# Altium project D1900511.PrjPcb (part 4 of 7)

## Sheet ISC_R5_SH3.SchDoc: ISC System Wiring Diagram
size B; DrawnBy: Filiberto Clara; Engineer: Filiberto Clara; Organization: LIGO Laboratory; Address1: California Institute of Technology; Address2: Massachusetts Institute of Technology; DocumentNumber: D1900511; Revision: V11; SheetNumber: 21; SheetTotal: 39
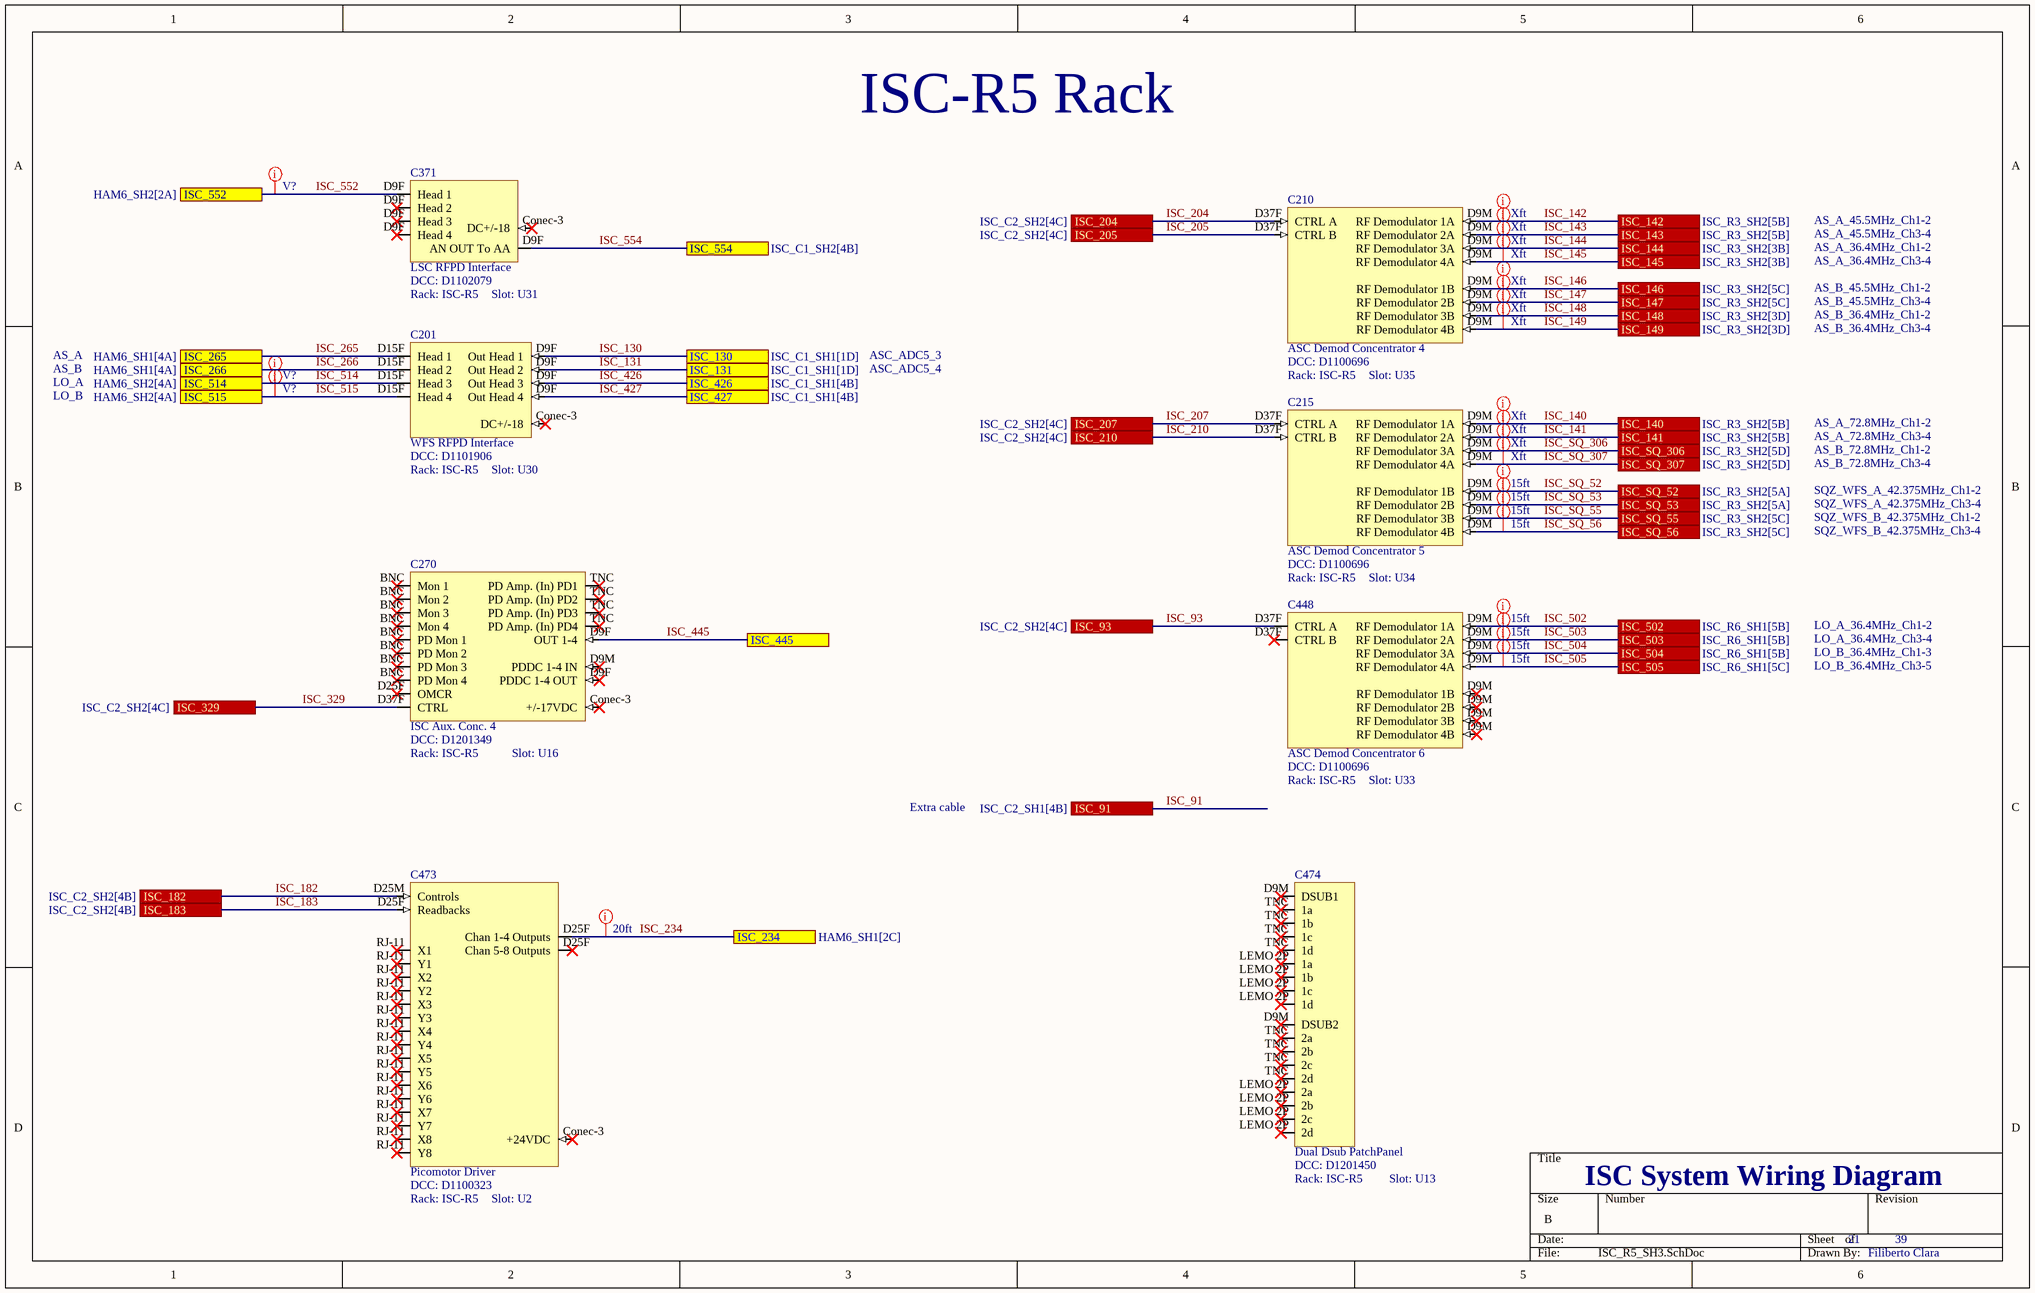
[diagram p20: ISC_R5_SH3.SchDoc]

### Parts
C201  WFS RFPD Interface  DCC: D1101906  Rack: ISC-R5  Slot: U30
C210  ASC Demod Concentrator 4  DCC: D1100696  Rack: ISC-R5  Slot: U35
C215  ASC Demod Concentrator 5  DCC: D1100696  Rack: ISC-R5  Slot: U34
C270  ISC Aux. Conc. 4  DCC: D1201349  Rack: ISC-R5  Slot: U16
C371  LSC RFPD Interface  DCC: D1102079  Rack: ISC-R5  Slot: U31
C448  ASC Demod Concentrator 6  DCC: D1100696  Rack: ISC-R5  Slot: U33
C473  Picomotor Driver  DCC: D1100323  Rack: ISC-R5  Slot: U2
C474  Dual Dsub PatchPanel  DCC: D1201450  Rack: ISC-R5  Slot: U13

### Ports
ISC_91 (see ISC_C2_SH1[4B]), ISC_93 (see ISC_C2_SH2[4C]), ISC_130 (see ISC_C1_SH1[1D]), ISC_131 (see ISC_C1_SH1[1D]), ISC_140 (see ISC_R3_SH2[5B]), ISC_141 (see ISC_R3_SH2[5B]), ISC_142 (see ISC_R3_SH2[5B]), ISC_143 (see ISC_R3_SH2[5B]), ISC_144 (see ISC_R3_SH2[3B]), ISC_145 (see ISC_R3_SH2[3B]), ISC_146 (see ISC_R3_SH2[5C]), ISC_147 (see ISC_R3_SH2[5C]), ISC_148 (see ISC_R3_SH2[3D]), ISC_149 (see ISC_R3_SH2[3D]), ISC_182 (see ISC_C2_SH2[4B]), ISC_183 (see ISC_C2_SH2[4B]), ISC_204 (see ISC_C2_SH2[4C]), ISC_205 (see ISC_C2_SH2[4C]), ISC_207 (see ISC_C2_SH2[4C]), ISC_210 (see ISC_C2_SH2[4C]), ISC_234 (see HAM6_SH1[2C]), ISC_265 (see HAM6_SH1[4A]), ISC_266 (see HAM6_SH1[4A]), ISC_329 (see ISC_C2_SH2[4C]), ISC_426 (see ISC_C1_SH1[4B]), ISC_427 (see ISC_C1_SH1[4B]), ISC_445, ISC_502 (see ISC_R6_SH1[5B]), ISC_503 (see ISC_R6_SH1[5B]), ISC_504 (see ISC_R6_SH1[5B]), ISC_505 (see ISC_R6_SH1[5C]), ISC_514 (see HAM6_SH2[4A]), ISC_515 (see HAM6_SH2[4A]), ISC_552 (see HAM6_SH2[2A]), ISC_554 (see ISC_C1_SH2[4B]), ISC_SQ_52 (see ISC_R3_SH2[5A]), ISC_SQ_53 (see ISC_R3_SH2[5A]), ISC_SQ_55 (see ISC_R3_SH2[5C]), ISC_SQ_56 (see ISC_R3_SH2[5C]), ISC_SQ_306 (see ISC_R3_SH2[5D]), ISC_SQ_307 (see ISC_R3_SH2[5D])

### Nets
ISC_93: C448.D37F(CTRL_A) ; port ISC_93
ISC_130: C201.D9F(Out_Head_1) ; port ISC_130
ISC_131: C201.D9F(Out_Head_2) ; port ISC_131
ISC_140: C215.D9M(RF_Demodulator_1A) ; port ISC_140
ISC_141: C215.D9M(RF_Demodulator_2A) ; port ISC_141
ISC_142: C210.D9M(RF_Demodulator_1A) ; port ISC_142
ISC_143: C210.D9M(RF_Demodulator_2A) ; port ISC_143
ISC_144: C210.D9M(RF_Demodulator_3A) ; port ISC_144
ISC_145: C210.D9M(RF_Demodulator_4A) ; port ISC_145
ISC_146: C210.D9M(RF_Demodulator_1B) ; port ISC_146
ISC_147: C210.D9M(RF_Demodulator_2B) ; port ISC_147
ISC_148: C210.D9M(RF_Demodulator_3B) ; port ISC_148
ISC_149: C210.D9M(RF_Demodulator_4B) ; port ISC_149
ISC_182: C473.D25M(Controls) ; port ISC_182
ISC_183: C473.D25F(Readbacks) ; port ISC_183
ISC_204: C210.D37F(CTRL_A) ; port ISC_204
ISC_205: C210.D37F(CTRL_B) ; port ISC_205
ISC_207: C215.D37F(CTRL_A) ; port ISC_207
ISC_210: C215.D37F(CTRL_B) ; port ISC_210
ISC_234: C473.D25F(Chan_1-4_Outputs) ; port ISC_234
ISC_265: C201.D15F(Head_1) ; port ISC_265
ISC_266: C201.D15F(Head_2) ; port ISC_266
ISC_329: C270.D37F(CTRL) ; port ISC_329
ISC_426: C201.D9F(Out_Head_3) ; port ISC_426
ISC_427: C201.D9F(Out_Head_4) ; port ISC_427
ISC_445: C270.D9F(PDDC_1-4_OUT) ; port ISC_445
ISC_502: C448.D9M(RF_Demodulator_1A) ; port ISC_502
ISC_503: C448.D9M(RF_Demodulator_2A) ; port ISC_503
ISC_504: C448.D9M(RF_Demodulator_3A) ; port ISC_504
ISC_505: C448.D9M(RF_Demodulator_4A) ; port ISC_505
ISC_514: C201.D15F(Head_3) ; port ISC_514
ISC_515: C201.D15F(Head_4) ; port ISC_515
ISC_552: C371.D9F(Head_1) ; port ISC_552
ISC_554: C371.D9F(AN_OUT_To_AA) ; port ISC_554
ISC_SQ_52: C215.D9M(RF_Demodulator_1B) ; port ISC_SQ_52
ISC_SQ_53: C215.D9M(RF_Demodulator_2B) ; port ISC_SQ_53
ISC_SQ_55: C215.D9M(RF_Demodulator_3B) ; port ISC_SQ_55
ISC_SQ_56: C215.D9M(RF_Demodulator_4B) ; port ISC_SQ_56
ISC_SQ_306: C215.D9M(RF_Demodulator_3A) ; port ISC_SQ_306
ISC_SQ_307: C215.D9M(RF_Demodulator_4A) ; port ISC_SQ_307

Not connected (* = marked no-connect by the designer): C201 Conec-3(DC+/-18)*; C270 BNC(PD_Mon_1)* Conec-3(+/-17VDC)* D9M(PDDC_1-4_IN)* D25F(OMCR)* TNC(PD_Amp._(In)_PD1)*; C371 Conec-3(DC+/-18)*; C473 Conec-3(+24VDC)* RJ-11(X1)*; C474 D9M(DSUB1)* LEMO 2P(1a)* TNC(1a)*

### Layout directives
Length: V?: ISC_514, ISC_515, ISC_552
Length: 20ft: ISC_234
Length: 15ft: ISC_502, ISC_503, ISC_504, ISC_505, ISC_SQ_52, ISC_SQ_53, ISC_SQ_55, ISC_SQ_56
Length: Xft: ISC_140, ISC_141, ISC_142, ISC_143, ISC_144, ISC_145, ISC_146, ISC_147, ISC_148, ISC_149, ISC_SQ_306, ISC_SQ_307

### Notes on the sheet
- ISC-R5 Rack
- AS_A_45.5MHz_Ch1-2
- AS_A_45.5MHz_Ch3-4
- AS_A_36.4MHz_Ch1-2
- AS_A_36.4MHz_Ch3-4
- AS_B_45.5MHz_Ch1-2
- AS_A
- AS_B
- ASC_ADC5_3
- ASC_ADC5_4
- AS_B_45.5MHz_Ch3-4
- AS_B_36.4MHz_Ch1-2
- AS_B_36.4MHz_Ch3-4
- LO_A
- LO_B
- AS_A_72.8MHz_Ch1-2
- AS_A_72.8MHz_Ch3-4
- AS_B_72.8MHz_Ch1-2
- AS_B_72.8MHz_Ch3-4
- SQZ_WFS_A_42.375MHz_Ch1-2
- SQZ_WFS_A_42.375MHz_Ch3-4
- SQZ_WFS_B_42.375MHz_Ch1-2
- SQZ_WFS_B_42.375MHz_Ch3-4
- LO_A_36.4MHz_Ch1-2
- LO_A_36.4MHz_Ch3-4
- LO_B_36.4MHz_Ch1-3
- LO_B_36.4MHz_Ch3-5
- Extra cable

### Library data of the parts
C201 = WFS RFPD Interface: Serial: Sxxxxxxx; System: ISC
C210 C215 C448 = ASC Demod Concentrator: Serial: Sxxxxxxx; System: ISC
C270 = ISC Aux. Conc. 4: Serial: Sxxxxxxx
C371 = LSC RFPD Interface: Serial: Sxxxxxxx; System: ISC
C473 = Picomotor Driver: Serial: Sxxxxxxx; System: ISC
C474 = Dual Dsub PatchPanel: Serial: Sxxxxxxx; System: ISC

## Sheet ISC_R6_SH1.SchDoc: ISC System Wiring Diagram
size B; DrawnBy: Filiberto Clara; Engineer: Filiberto Clara; Organization: LIGO Laboratory; Address1: California Institute of Technology; Address2: Massachusetts Institute of Technology; DocumentNumber: D1900511; Revision: V11; SheetNumber: 22; SheetTotal: 39
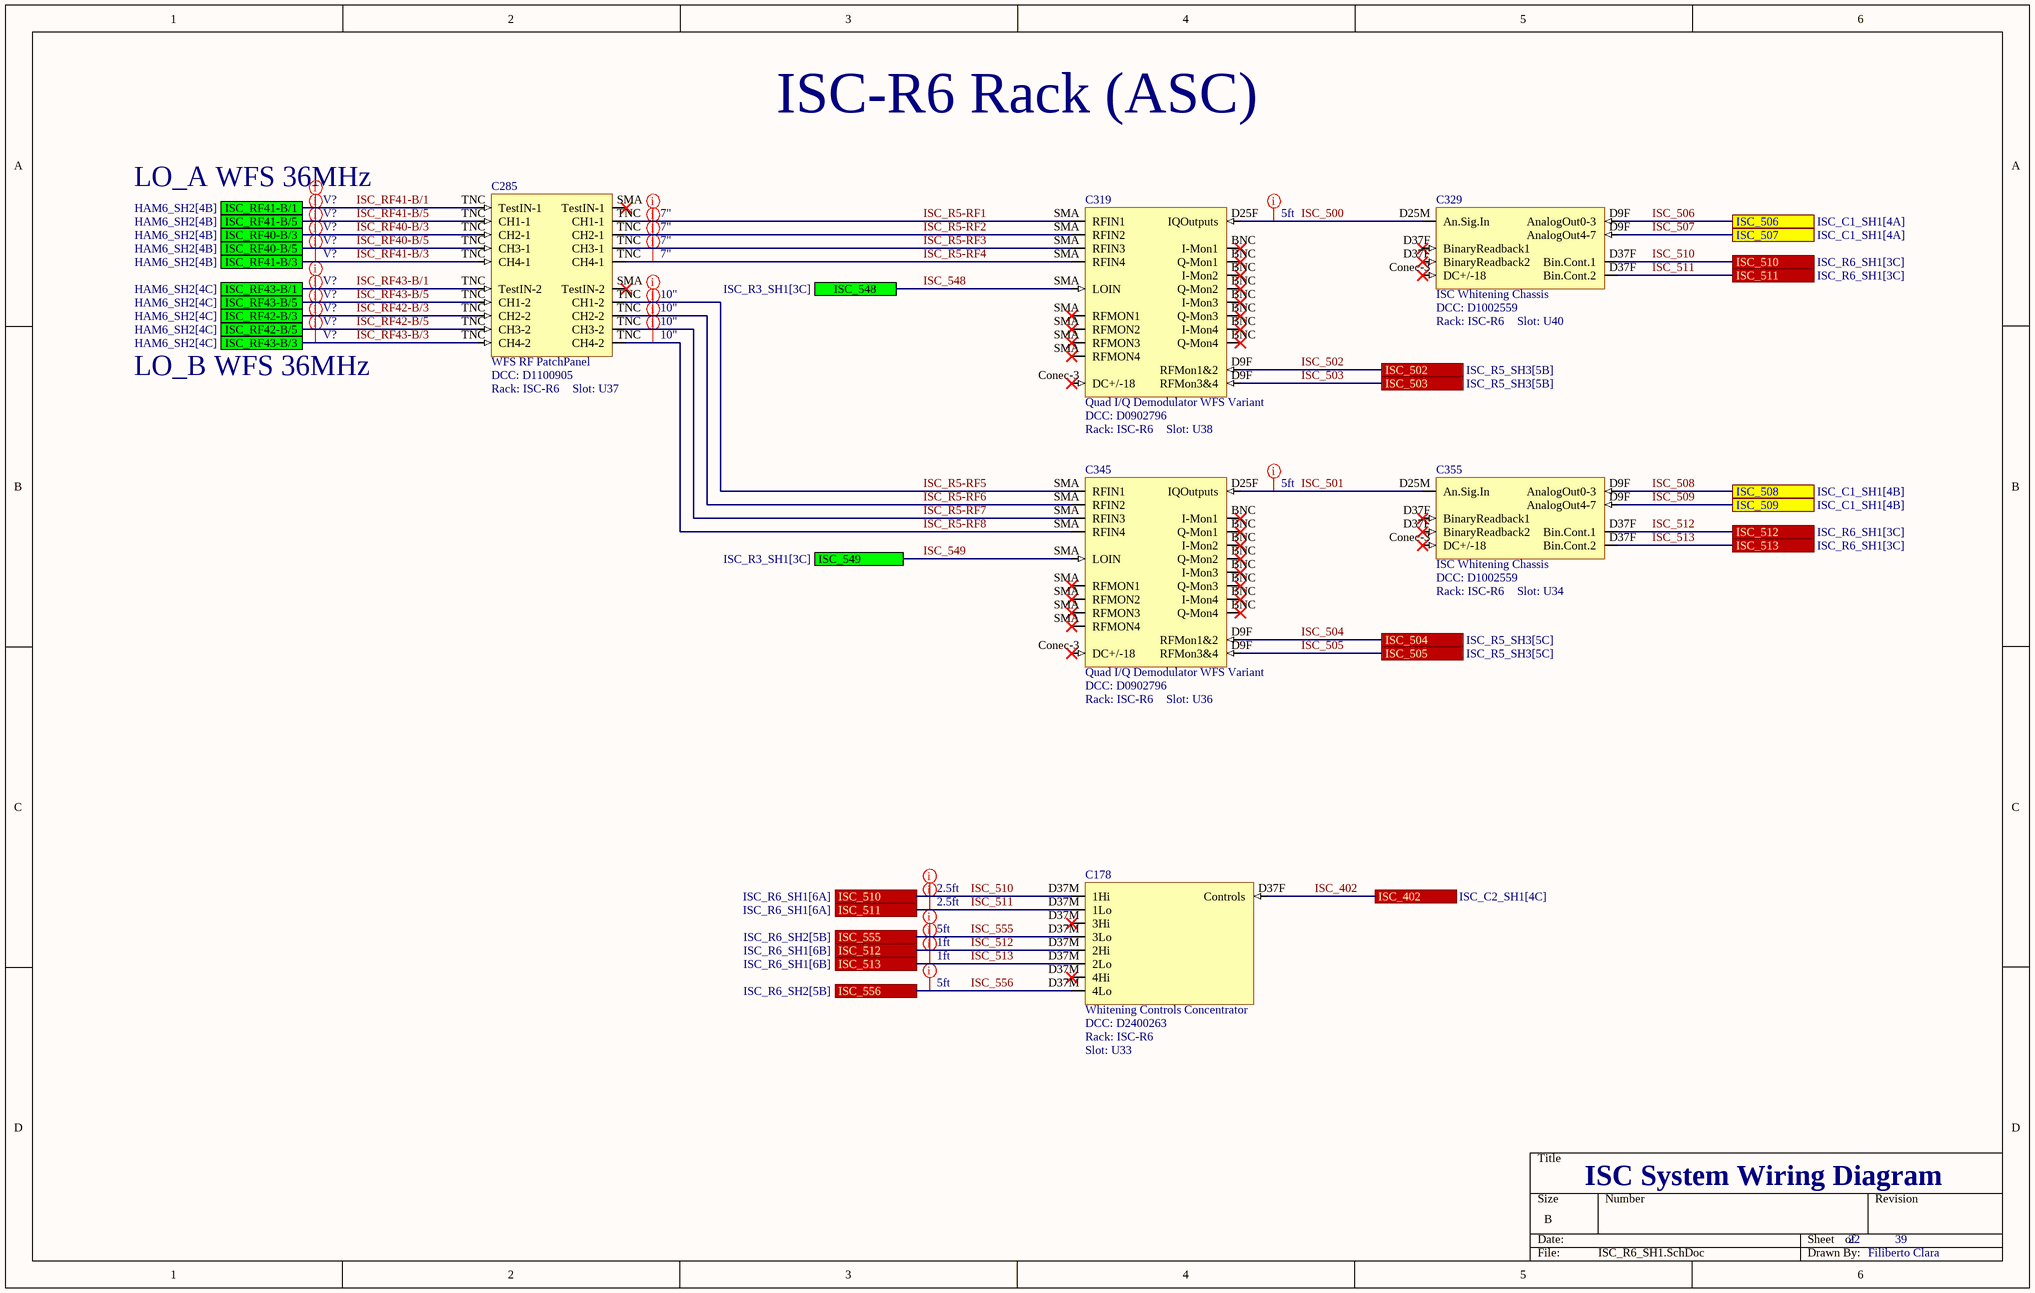
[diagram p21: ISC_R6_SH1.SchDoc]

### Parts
C178  Whitening Controls Concentrator  DCC: D2400263  Rack: ISC-R6  Slot: U33
C285  WFS RF PatchPanel  DCC: D1100905  Rack: ISC-R6  Slot: U37
C319  Quad I/Q Demodulator WFS Variant  DCC: D0902796  Rack: ISC-R6  Slot: U38
C329  ISC Whitening Chassis  DCC: D1002559  Rack: ISC-R6  Slot: U40
C345  Quad I/Q Demodulator WFS Variant  DCC: D0902796  Rack: ISC-R6  Slot: U36
C355  ISC Whitening Chassis  DCC: D1002559  Rack: ISC-R6  Slot: U34

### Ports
ISC_402 (see ISC_C2_SH1[4C]), ISC_502 (see ISC_R5_SH3[5B]), ISC_503 (see ISC_R5_SH3[5B]), ISC_504 (see ISC_R5_SH3[5C]), ISC_505 (see ISC_R5_SH3[5C]), ISC_506 (see ISC_C1_SH1[4A]), ISC_507 (see ISC_C1_SH1[4A]), ISC_508 (see ISC_C1_SH1[4B]), ISC_509 (see ISC_C1_SH1[4B]), ISC_510 (see ISC_R6_SH1[3C]), ISC_510 (see ISC_R6_SH1[6A]), ISC_511 (see ISC_R6_SH1[3C]), ISC_511 (see ISC_R6_SH1[6A]), ISC_512 (see ISC_R6_SH1[3C]), ISC_512 (see ISC_R6_SH1[6B]), ISC_513 (see ISC_R6_SH1[3C]), ISC_513 (see ISC_R6_SH1[6B]), ISC_548 (see ISC_R3_SH1[3C]), ISC_549 (see ISC_R3_SH1[3C]), ISC_555 (see ISC_R6_SH2[5B]), ISC_556 (see ISC_R6_SH2[5B]), ISC_RF40-B/3 (see HAM6_SH2[4B]), ISC_RF40-B/5 (see HAM6_SH2[4B]), ISC_RF41-B/1 (see HAM6_SH2[4B]), ISC_RF41-B/3 (see HAM6_SH2[4B]), ISC_RF41-B/5 (see HAM6_SH2[4B]), ISC_RF42-B/3 (see HAM6_SH2[4C]), ISC_RF42-B/5 (see HAM6_SH2[4C]), ISC_RF43-B/1 (see HAM6_SH2[4C]), ISC_RF43-B/3 (see HAM6_SH2[4C]), ISC_RF43-B/5 (see HAM6_SH2[4C])

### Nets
ISC_402: C178.D37F(Controls) ; port ISC_402
ISC_500: C319.D25F(IQOutputs) C329.D25M(An.Sig.In)
ISC_501: C345.D25F(IQOutputs) C355.D25M(An.Sig.In)
ISC_502: C319.D9F(RFMon1&2) ; port ISC_502
ISC_503: C319.D9F(RFMon3&4) ; port ISC_503
ISC_504: C345.D9F(RFMon1&2) ; port ISC_504
ISC_505: C345.D9F(RFMon3&4) ; port ISC_505
ISC_506: C329.D9F(AnalogOut0-3) ; port ISC_506
ISC_507: C329.D9F(AnalogOut4-7) ; port ISC_507
ISC_508: C355.D9F(AnalogOut0-3) ; port ISC_508
ISC_509: C355.D9F(AnalogOut4-7) ; port ISC_509
ISC_510: C178.D37M(1Hi) C329.D37F(BinaryReadback1) ; port ISC_510
ISC_511: C178.D37M(1Lo) C329.D37F(Bin.Cont.2) ; port ISC_511
ISC_512: C178.D37M(2Hi) C355.D37F(BinaryReadback1) ; port ISC_512
ISC_513: C178.D37M(2Lo) C355.D37F(Bin.Cont.2) ; port ISC_513
ISC_548: C319.SMA(LOIN) ; port ISC_548
ISC_549: C345.SMA(LOIN) ; port ISC_549
ISC_555: C178.D37M(3Lo) ; port ISC_555
ISC_556: C178.D37M(4Lo) ; port ISC_556
ISC_R5-RF1: C285.TNC(CH1-1) C319.SMA(RFIN1)
ISC_R5-RF2: C285.TNC(CH2-1) C319.SMA(RFIN2)
ISC_R5-RF3: C285.TNC(CH3-1) C319.SMA(RFIN3)
ISC_R5-RF4: C285.TNC(CH4-1) C319.SMA(RFIN4)
ISC_R5-RF5: C285.TNC(CH1-2) C345.SMA(RFIN1)
ISC_R5-RF6: C285.TNC(CH2-2) C345.SMA(RFIN2)
ISC_R5-RF7: C285.TNC(CH3-2) C345.SMA(RFIN3)
ISC_R5-RF8: C285.TNC(CH4-2) C345.SMA(RFIN4)
ISC_RF40-B/3: C285.TNC(CH2-1) ; port ISC_RF40-B/3
ISC_RF40-B/5: C285.TNC(CH3-1) ; port ISC_RF40-B/5
ISC_RF41-B/1: C285.TNC(TestIN-1) ; port ISC_RF41-B/1
ISC_RF41-B/3: C285.TNC(CH4-1) ; port ISC_RF41-B/3
ISC_RF41-B/5: C285.TNC(CH1-1) ; port ISC_RF41-B/5
ISC_RF42-B/3: C285.TNC(CH2-2) ; port ISC_RF42-B/3
ISC_RF42-B/5: C285.TNC(CH3-2) ; port ISC_RF42-B/5
ISC_RF43-B/1: C285.TNC(TestIN-2) ; port ISC_RF43-B/1
ISC_RF43-B/3: C285.TNC(CH4-2) ; port ISC_RF43-B/3
ISC_RF43-B/5: C285.TNC(CH1-2) ; port ISC_RF43-B/5

Not connected (* = marked no-connect by the designer): C285 SMA(TestIN-1)*; C319 BNC(I-Mon1)* Conec-3(DC+/-18)*; C329 Conec-3(DC+/-18)*; C345 BNC(I-Mon1)* Conec-3(DC+/-18)*; C355 Conec-3(DC+/-18)*

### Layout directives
Length: 10": ISC_R5-RF5, ISC_R5-RF6, ISC_R5-RF7, ISC_R5-RF8
Length: V?: ISC_RF40-B/3, ISC_RF40-B/5, ISC_RF41-B/1, ISC_RF41-B/3, ISC_RF41-B/5, ISC_RF42-B/3, ISC_RF42-B/5, ISC_RF43-B/1, ISC_RF43-B/3, ISC_RF43-B/5
Length: 5ft: ISC_500, ISC_501, ISC_555, ISC_556
Length: 7": ISC_R5-RF1, ISC_R5-RF2, ISC_R5-RF3, ISC_R5-RF4
Length: 2.5ft: ISC_510, ISC_511
Length: 1ft: ISC_512, ISC_513

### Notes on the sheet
- ISC-R6 Rack (ASC)
- LO_A WFS 36MHz
- LO_B WFS 36MHz

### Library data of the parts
C178 = Whitening Controls Concentrator: Serial: Sxxxxxxx; System: ISC
C285 = WFS RFPD PatchPanel: Serial: Sxxxxxxx; System: ISC
C319 C345 = QuadIQdemod_WFS: Serial: Sxxxxxxx; System: ISC
C329 C355 = ISC Whitening: Serial: Sxxxxxxx

## Sheet ISC_R6_SH2.SchDoc: ISC System Wiring Diagram
size B; DrawnBy: Filiberto Clara; Engineer: Filiberto Clara; Organization: LIGO Laboratory; Address1: California Institute of Technology; Address2: Massachusetts Institute of Technology; DocumentNumber: D1900511; Revision: V11; SheetNumber: 23; SheetTotal: 39
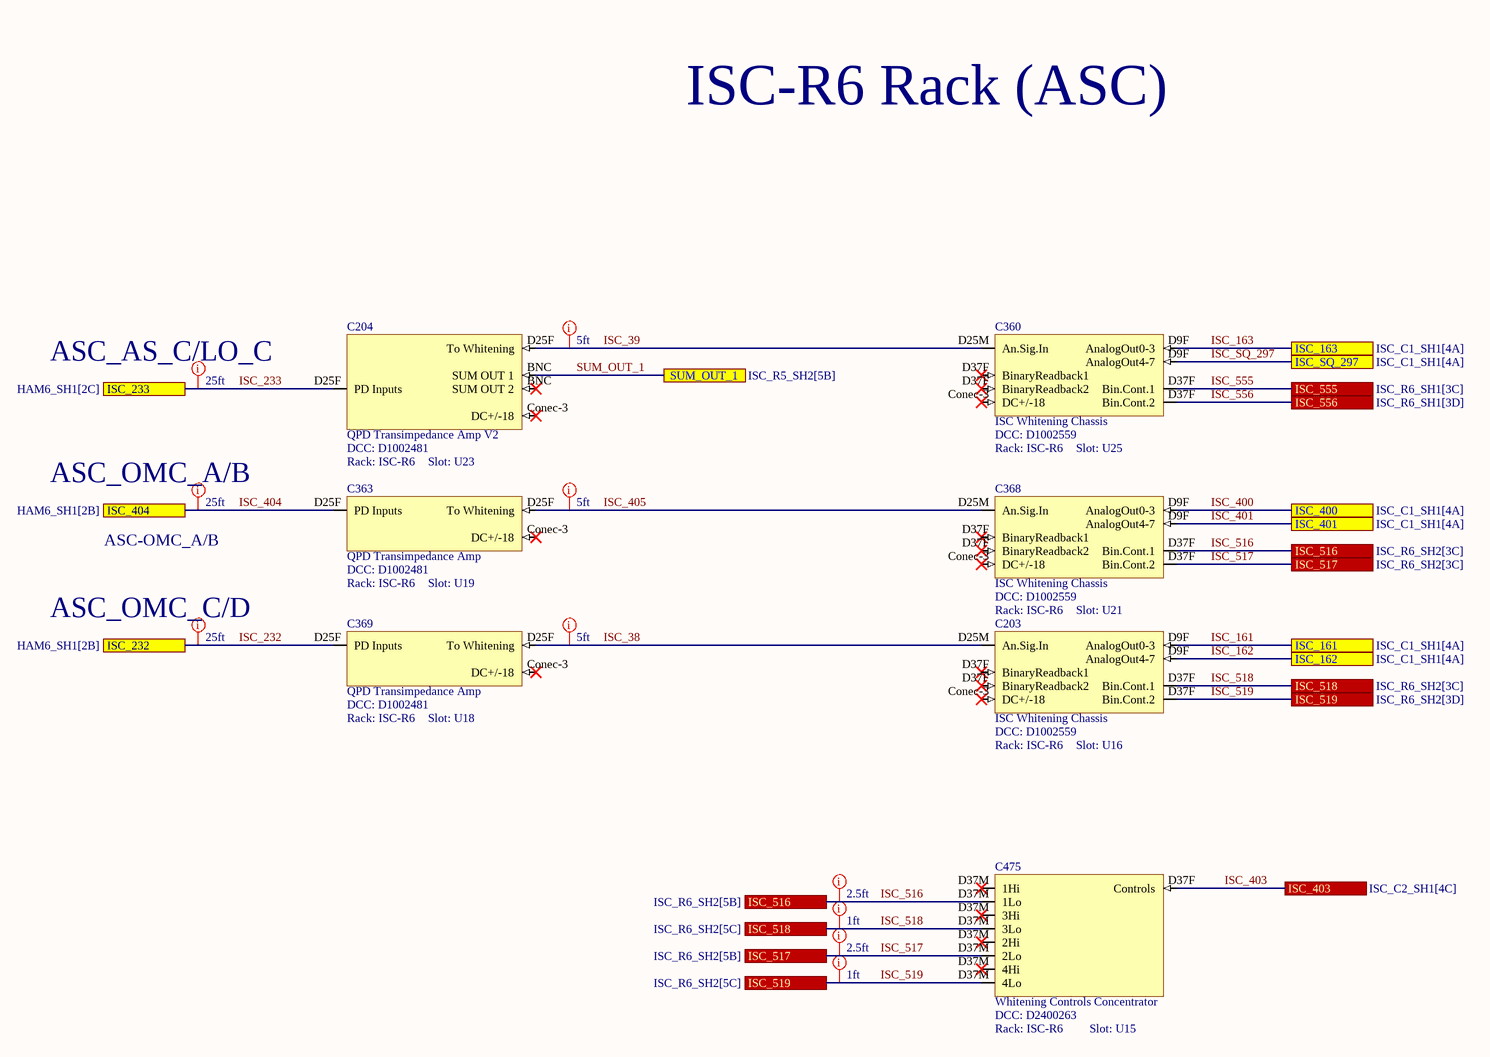
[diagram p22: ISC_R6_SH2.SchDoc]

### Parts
C203  ISC Whitening Chassis  DCC: D1002559  Rack: ISC-R6  Slot: U16
C204  QPD Transimpedance Amp V2  DCC: D1002481  Rack: ISC-R6  Slot: U23
C360  ISC Whitening Chassis  DCC: D1002559  Rack: ISC-R6  Slot: U25
C363  QPD Transimpedance Amp  DCC: D1002481  Rack: ISC-R6  Slot: U19
C368  ISC Whitening Chassis  DCC: D1002559  Rack: ISC-R6  Slot: U21
C369  QPD Transimpedance Amp  DCC: D1002481  Rack: ISC-R6  Slot: U18
C475  Whitening Controls Concentrator  DCC: D2400263  Rack: ISC-R6  Slot: U15

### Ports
ISC_161 (see ISC_C1_SH1[4A]), ISC_162 (see ISC_C1_SH1[4A]), ISC_163 (see ISC_C1_SH1[4A]), ISC_232 (see HAM6_SH1[2B]), ISC_233 (see HAM6_SH1[2C]), ISC_400 (see ISC_C1_SH1[4A]), ISC_401 (see ISC_C1_SH1[4A]), ISC_403 (see ISC_C2_SH1[4C]), ISC_404 (see HAM6_SH1[2B]), ISC_516 (see ISC_R6_SH2[3C]), ISC_516 (see ISC_R6_SH2[5B]), ISC_517 (see ISC_R6_SH2[3C]), ISC_517 (see ISC_R6_SH2[5B]), ISC_518 (see ISC_R6_SH2[3C]), ISC_518 (see ISC_R6_SH2[5C]), ISC_519 (see ISC_R6_SH2[3D]), ISC_519 (see ISC_R6_SH2[5C]), ISC_555 (see ISC_R6_SH1[3C]), ISC_556 (see ISC_R6_SH1[3D]), ISC_SQ_297 (see ISC_C1_SH1[4A]), SUM_OUT_1 (see ISC_R5_SH2[5B])

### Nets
ISC_38: C203.D25M(An.Sig.In) C369.D25F(To_Whitening)
ISC_39: C204.D25F(To_Whitening) C360.D25M(An.Sig.In)
ISC_161: C203.D9F(AnalogOut0-3) ; port ISC_161
ISC_162: C203.D9F(AnalogOut4-7) ; port ISC_162
ISC_163: C360.D9F(AnalogOut0-3) ; port ISC_163
ISC_232: C369.D25F(PD_Inputs) ; port ISC_232
ISC_233: C204.D25F(PD_Inputs) ; port ISC_233
ISC_400: C368.D9F(AnalogOut0-3) ; port ISC_400
ISC_401: C368.D9F(AnalogOut4-7) ; port ISC_401
ISC_403: C475.D37F(Controls) ; port ISC_403
ISC_404: C363.D25F(PD_Inputs) ; port ISC_404
ISC_405: C363.D25F(To_Whitening) C368.D25M(An.Sig.In)
ISC_516: C368.D37F(BinaryReadback1) C475.D37M(1Hi) ; port ISC_516
ISC_517: C368.D37F(Bin.Cont.2) C475.D37M(2Lo) ; port ISC_517
ISC_518: C203.D37F(BinaryReadback1) C475.D37M(3Lo) ; port ISC_518
ISC_519: C203.D37F(Bin.Cont.2) C475.D37M(4Lo) ; port ISC_519
ISC_555: C360.D37F(BinaryReadback1) ; port ISC_555
ISC_556: C360.D37F(Bin.Cont.2) ; port ISC_556
ISC_SQ_297: C360.D9F(AnalogOut4-7) ; port ISC_SQ_297
SUM_OUT_1: C204.BNC(SUM_OUT_1) ; port SUM_OUT_1

Not connected (* = marked no-connect by the designer): C203 Conec-3(DC+/-18)*; C204 Conec-3(DC+/-18)*; C360 Conec-3(DC+/-18)*; C363 Conec-3(DC+/-18)*; C368 Conec-3(DC+/-18)*; C369 Conec-3(DC+/-18)*

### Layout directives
Length: 5ft: ISC_38, ISC_39, ISC_405
Length: 25ft: ISC_232, ISC_233, ISC_404
Length: 2.5ft: ISC_516, ISC_517
Length: 1ft: ISC_518, ISC_519

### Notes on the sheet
- ISC-R6 Rack (ASC)
- ASC_AS_C/LO_C
- ASC_OMC_A/B
- ASC-OMC_A/B
- ASC_OMC_C/D

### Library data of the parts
C203 C360 C368 = ISC Whitening: Serial: Sxxxxxxx
C204 = QPD Transimpedance Amp V2: Serial: Sxxxxxxx; System: ISC
C363 C369 = QPD Transimpedance Amp: Serial: Sxxxxxxx; System: ISC
C475 = Whitening Controls Concentrator: Serial: Sxxxxxxx; System: ISC

## Sheet ISCT1_SH1.SchDoc: ISC System Wiring Diagram
size B; DrawnBy: Filiberto Clara; Engineer: Filiberto Clara; Organization: LIGO Laboratory; Address1: California Institute of Technology; Address2: Massachusetts Institute of Technology; DocumentNumber: D1900511; Revision: V11; SheetNumber: 24; SheetTotal: 39
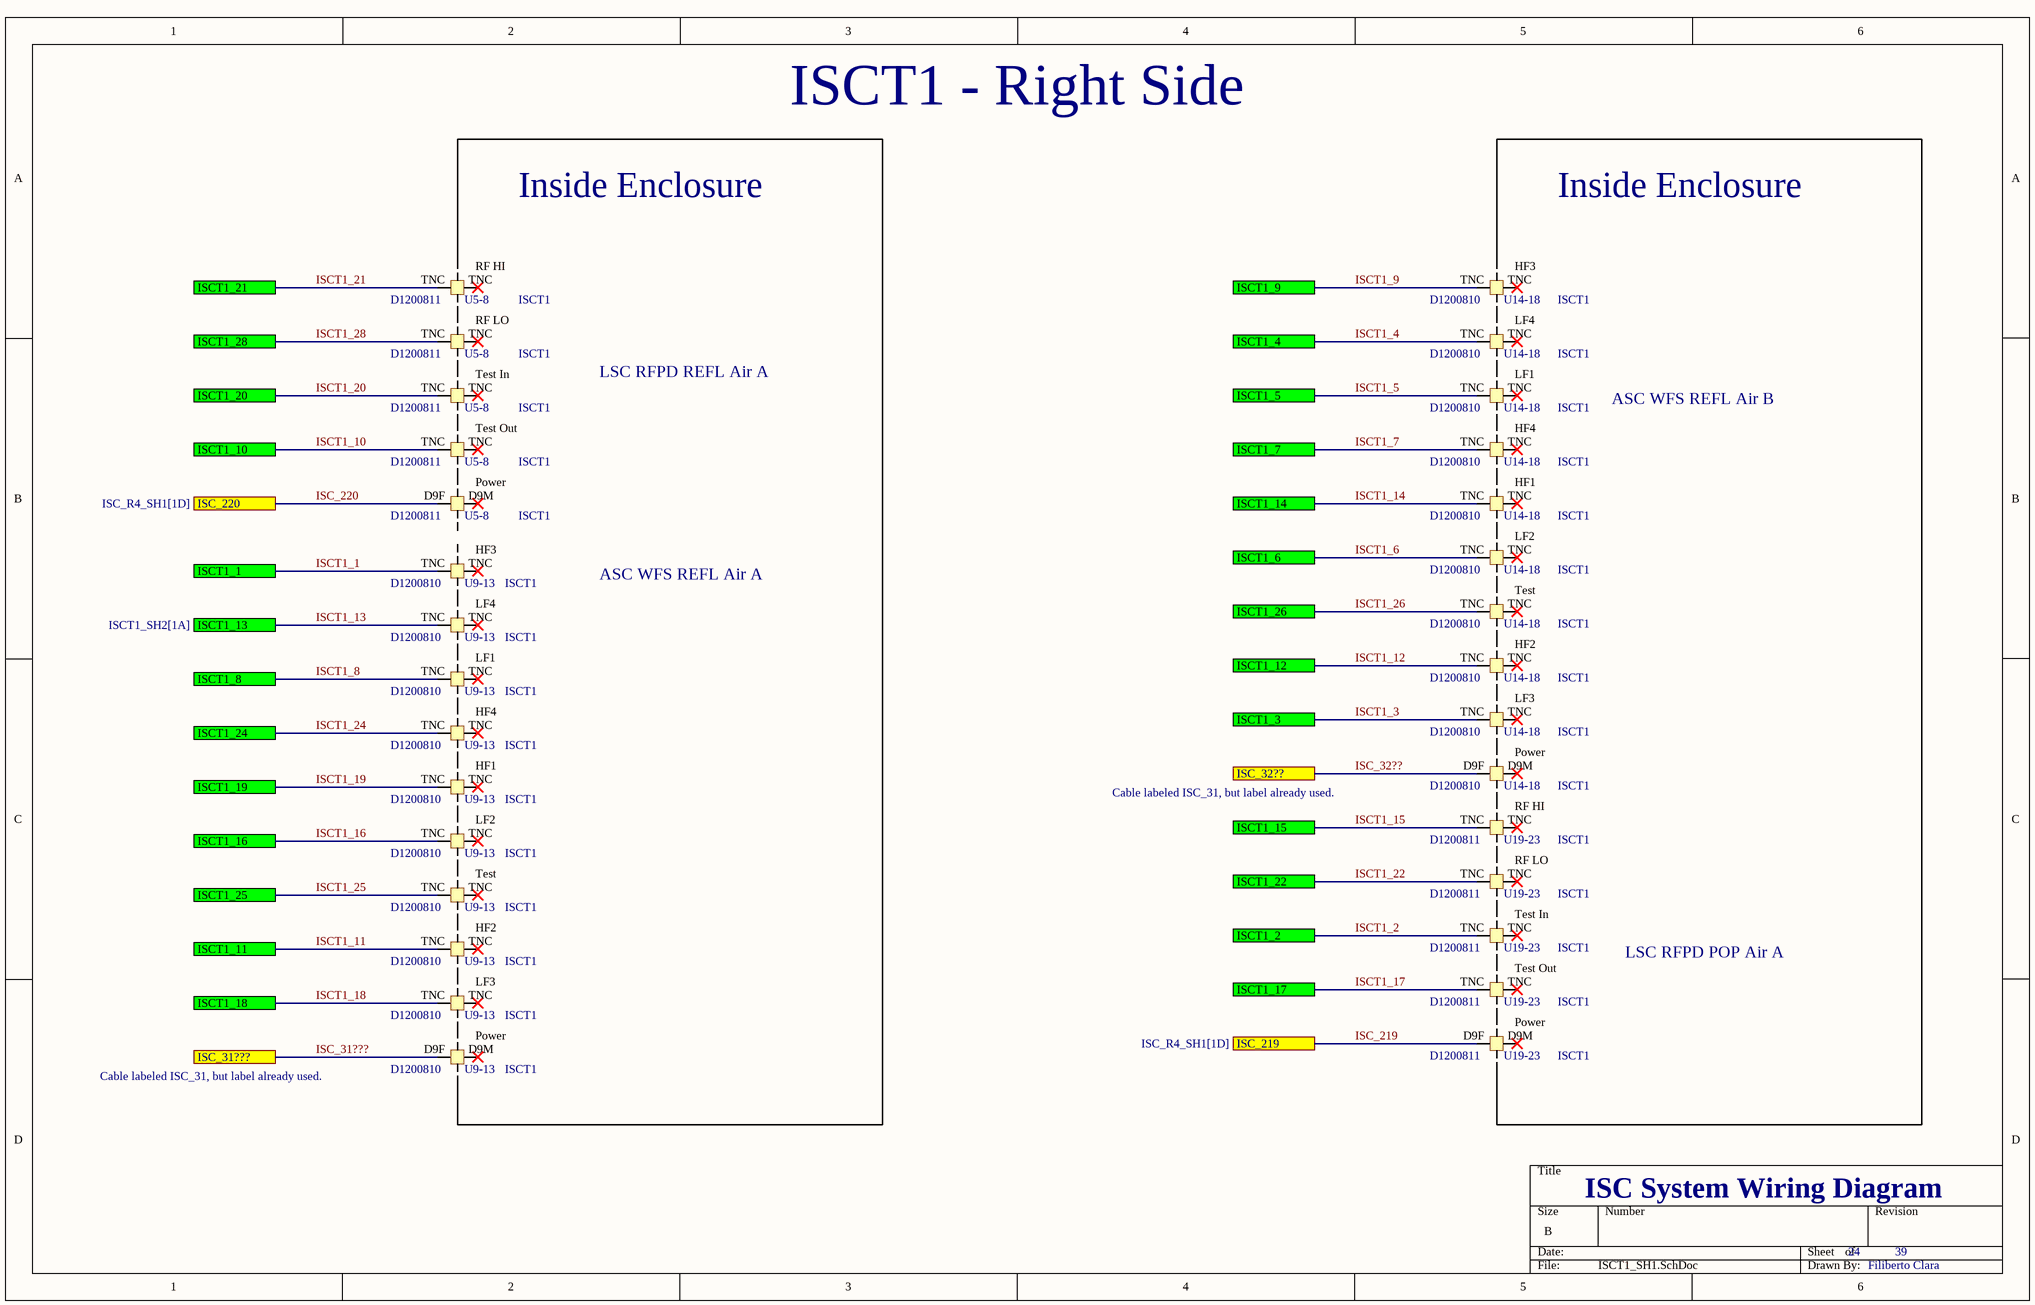
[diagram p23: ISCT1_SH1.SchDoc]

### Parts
C_ISCT1_1  DCC: D1200811  Rack: ISCT1  Slot: U5-8  (hidden comment: Patch Panel Dual Frequency LSC RFPD)  (parts A,B,C,D,E of 5)
C_ISCT1_2  DCC: D1200810  Rack: ISCT1  Slot: U9-13  (hidden comment: Patch Panel Dual Frequency WFS RFPD)  (parts A,B,C,D,E,F,G,H,I,J of 10)
C_ISCT1_3  DCC: D1200810  Rack: ISCT1  Slot: U14-18  (hidden comment: Patch Panel Dual Frequency WFS RFPD)  (parts A,B,C,D,E,F,G,H,I,J of 10)
C_ISCT1_4  DCC: D1200811  Rack: ISCT1  Slot: U19-23  (hidden comment: Patch Panel Dual Frequency LSC RFPD)  (parts A,B,C,D,E of 5)

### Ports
ISC_31???, ISC_32??, ISC_219 (see ISC_R4_SH1[1D]), ISC_220 (see ISC_R4_SH1[1D]), ISCT1_1, ISCT1_2, ISCT1_3, ISCT1_4, ISCT1_5, ISCT1_6, ISCT1_7, ISCT1_8, ISCT1_9, ISCT1_10, ISCT1_11, ISCT1_12, ISCT1_13 (see ISCT1_SH2[1A]), ISCT1_14, ISCT1_15, ISCT1_16, ISCT1_17, ISCT1_18, ISCT1_19, ISCT1_20, ISCT1_21, ISCT1_22, ISCT1_24, ISCT1_25, ISCT1_26, ISCT1_28

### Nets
ISC_31???: C_ISCT1_2.D9F(Power) ; port ISC_31???
ISC_32??: C_ISCT1_3.D9F(Power) ; port ISC_32??
ISC_219: C_ISCT1_4.D9F(Power) ; port ISC_219
ISC_220: C_ISCT1_1.D9F(Power) ; port ISC_220
ISCT1_1: C_ISCT1_2.TNC(H3F) ; port ISCT1_1
ISCT1_2: C_ISCT1_4.TNC(TestIn) ; port ISCT1_2
ISCT1_3: C_ISCT1_3.TNC(LF3) ; port ISCT1_3
ISCT1_4: C_ISCT1_3.TNC(LF4) ; port ISCT1_4
ISCT1_5: C_ISCT1_3.TNC(LF1) ; port ISCT1_5
ISCT1_6: C_ISCT1_3.TNC(LF2) ; port ISCT1_6
ISCT1_7: C_ISCT1_3.TNC(HF4) ; port ISCT1_7
ISCT1_8: C_ISCT1_2.TNC(LF1) ; port ISCT1_8
ISCT1_9: C_ISCT1_3.TNC(H3F) ; port ISCT1_9
ISCT1_10: C_ISCT1_1.TNC(TestOut) ; port ISCT1_10
ISCT1_11: C_ISCT1_2.TNC(HF2) ; port ISCT1_11
ISCT1_12: C_ISCT1_3.TNC(HF2) ; port ISCT1_12
ISCT1_13: C_ISCT1_2.TNC(LF4) ; port ISCT1_13
ISCT1_14: C_ISCT1_3.TNC(HF1) ; port ISCT1_14
ISCT1_15: C_ISCT1_4.TNC(RFHI) ; port ISCT1_15
ISCT1_16: C_ISCT1_2.TNC(LF2) ; port ISCT1_16
ISCT1_17: C_ISCT1_4.TNC(TestOut) ; port ISCT1_17
ISCT1_18: C_ISCT1_2.TNC(LF3) ; port ISCT1_18
ISCT1_19: C_ISCT1_2.TNC(HF1) ; port ISCT1_19
ISCT1_20: C_ISCT1_1.TNC(TestIn) ; port ISCT1_20
ISCT1_21: C_ISCT1_1.TNC(RFHI) ; port ISCT1_21
ISCT1_22: C_ISCT1_4.TNC(RFLO) ; port ISCT1_22
ISCT1_24: C_ISCT1_2.TNC(HF4) ; port ISCT1_24
ISCT1_25: C_ISCT1_2.TNC(Test) ; port ISCT1_25
ISCT1_26: C_ISCT1_3.TNC(Test) ; port ISCT1_26
ISCT1_28: C_ISCT1_1.TNC(RFLO) ; port ISCT1_28

Not connected (* = marked no-connect by the designer): C_ISCT1_1 D9M(Power)*; C_ISCT1_2 D9M(Power)*; C_ISCT1_3 D9M(Power)*; C_ISCT1_4 D9M(Power)*

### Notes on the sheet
- ISCT1 - Right Side
- Inside Enclosure
- LSC RFPD REFL Air A
- ASC WFS REFL Air B
- ASC WFS REFL Air A
- Cable labeled ISC_31, but label already used.
- LSC RFPD POP Air A

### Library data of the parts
C_ISCT1_1 C_ISCT1_4 = Patch Panel Dual Frequency LSC RFPD: Patch Panel (D1200811); Serial: Sxxxxxxx; System: ISC
C_ISCT1_2 C_ISCT1_3 = Patch Panel Dual Frequency WFS RFPD: Patch Panel (D1200810); Serial: Sxxxxxxx; System: ISC

## Sheet ISCT1_SH2.SchDoc: ISC System Wiring Diagram
size B; DrawnBy: Filiberto Clara; Engineer: Filiberto Clara; Organization: LIGO Laboratory; Address1: California Institute of Technology; Address2: Massachusetts Institute of Technology; DocumentNumber: D1900511; Revision: V11; SheetNumber: 25; SheetTotal: 39
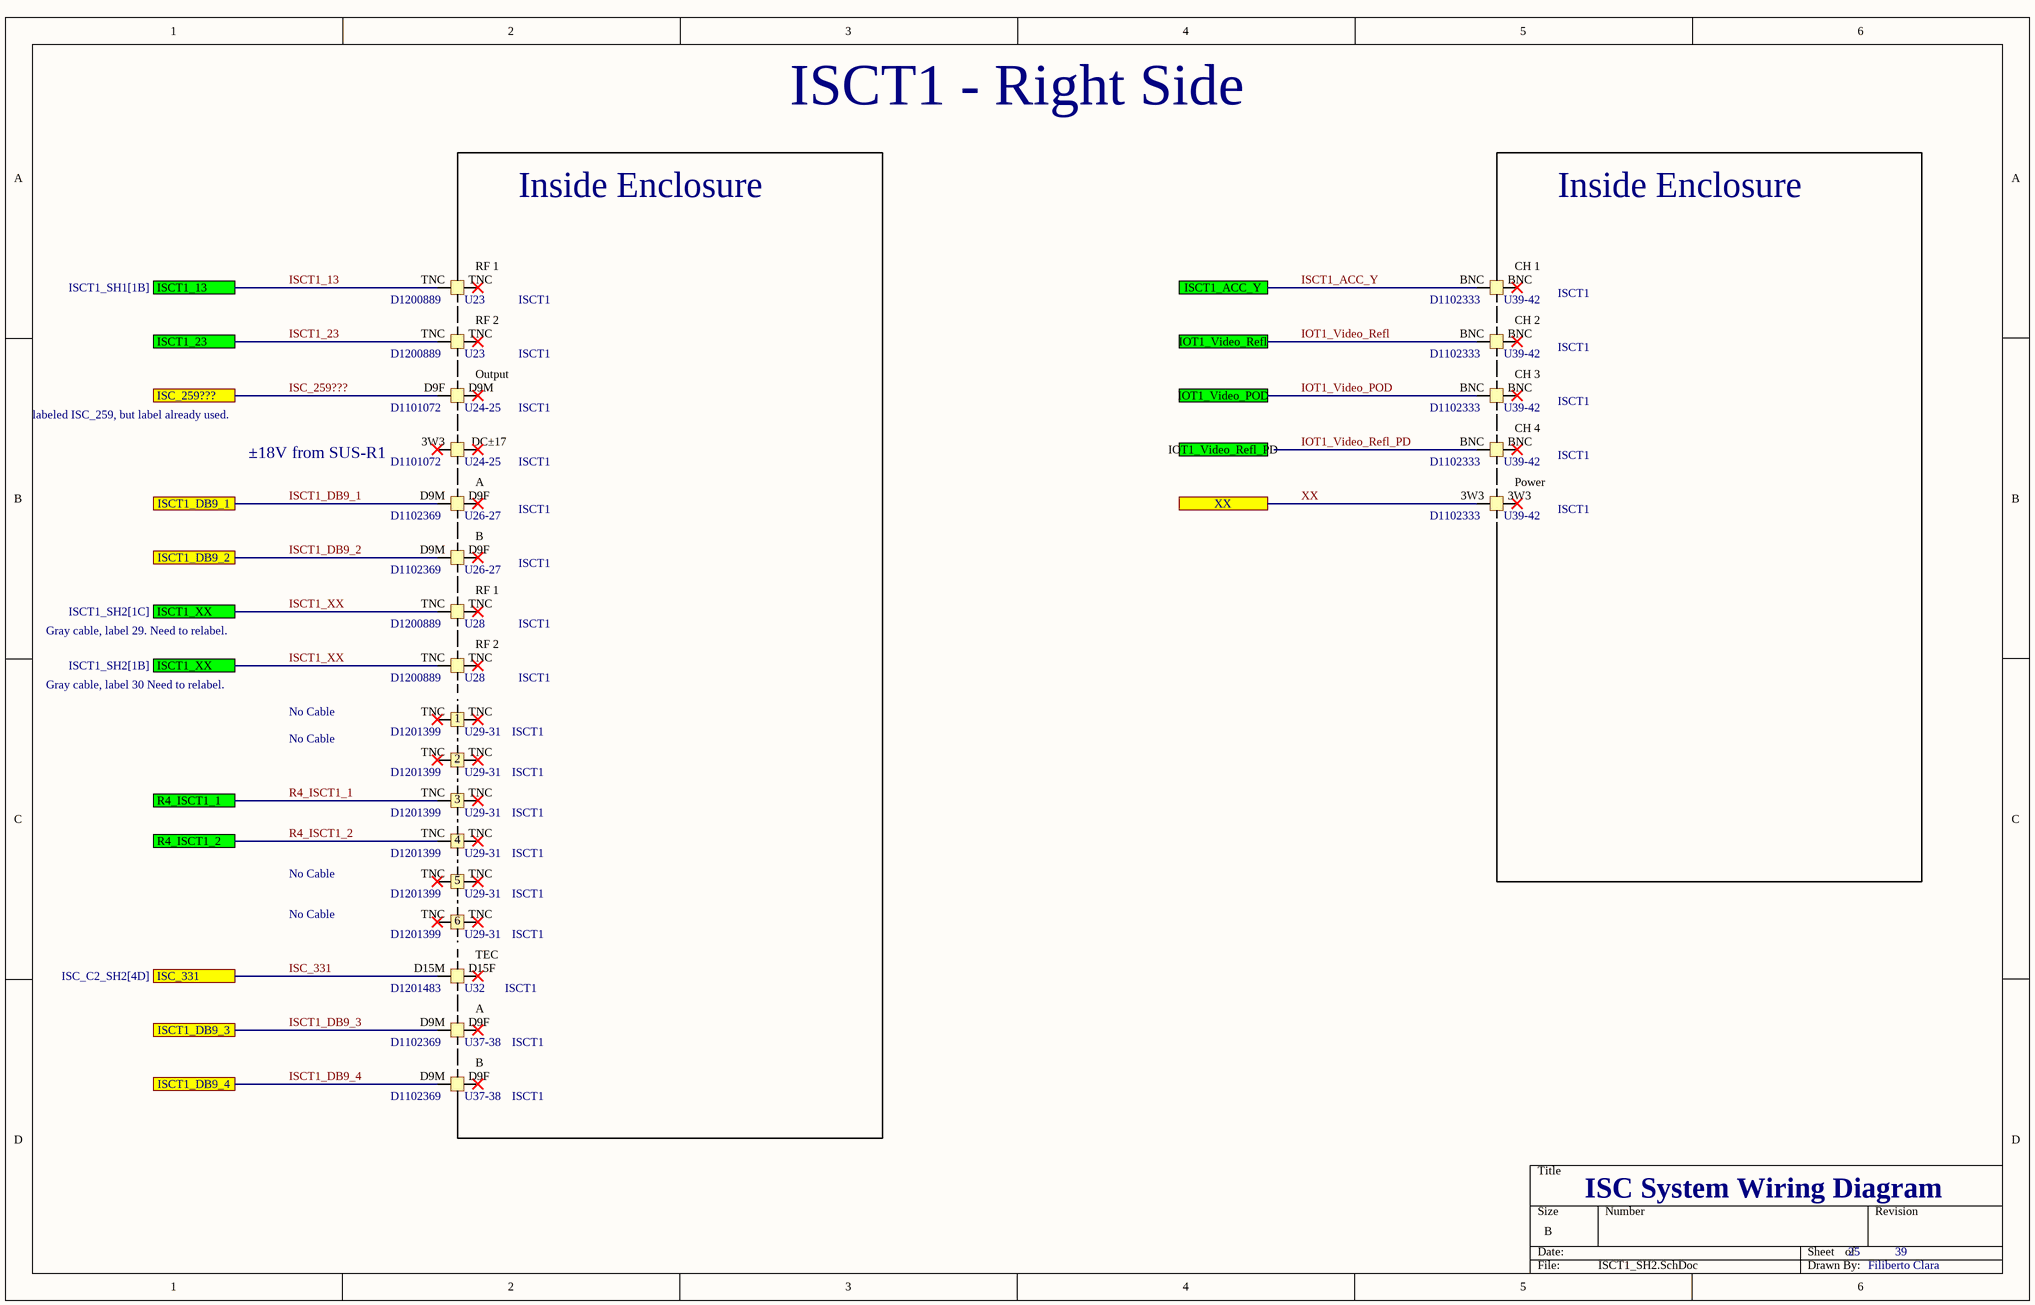
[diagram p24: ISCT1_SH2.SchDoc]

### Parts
C_ISCT1_5  DCC: D1200889  Rack: ISCT1  Slot: U23  (hidden comment: Patch Panel Broadband PD)  (parts A,B of 2)
C_ISCT1_6  DCC: D1101072  Rack: ISCT1  Slot: U24-25  (hidden comment: Patch Panel DCPD Interface)  (parts A,B of 2)
C_ISCT1_7  DCC: D1102369  Rack: ISCT1  Slot: U26-27  (hidden comment: Patch Panel Uniblitz Shutters)  (parts A,B of 2)
C_ISCT1_8  DCC: D1200889  Rack: ISCT1  Slot: U28  (hidden comment: Patch Panel Broadband PD)  (parts A,B of 2)
C_ISCT1_9  DCC: D1201399  Rack: ISCT1  Slot: U29-31  (hidden comment: Patch Panel DCPD)  (parts A,B,C,D,E,F of 6)
C_ISCT1_10  DCC: D1201483  Rack: ISCT1  Slot: U32  (hidden comment: Patch Panel TEC Driver)
C_ISCT1_11  DCC: D1102369  Rack: ISCT1  Slot: U37-38  (hidden comment: Patch Panel Uniblitz Shutters)  (parts A,B of 2)
C_ISCT1_12  DCC: D1102333  Rack: ISCT1  Slot: U39-42  (hidden comment: Patch Panel Analog Video)  (parts A,B,C,D,E of 5)

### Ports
IOT1_Video_POD, IOT1_Video_Refl, IOT1_Video_Refl_PD, ISC_259???, ISC_331 (see ISC_C2_SH2[4D]), ISCT1_13 (see ISCT1_SH1[1B]), ISCT1_23, ISCT1_ACC_Y, ISCT1_DB9_1, ISCT1_DB9_2, ISCT1_DB9_3, ISCT1_DB9_4, ISCT1_XX (see ISCT1_SH2[1B]), ISCT1_XX (see ISCT1_SH2[1C]), R4_ISCT1_1, R4_ISCT1_2, XX

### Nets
IOT1_Video_POD: C_ISCT1_12.BNC(CH_3) ; port IOT1_Video_POD
IOT1_Video_Refl: C_ISCT1_12.BNC(CH_2) ; port IOT1_Video_Refl
IOT1_Video_Refl_PD: C_ISCT1_12.BNC(CH_4)
ISC_259???: C_ISCT1_6.D9F(Output) ; port ISC_259???
ISC_331: C_ISCT1_10.D15M(TEC) ; port ISC_331
ISCT1_13: C_ISCT1_5.TNC(RF1) ; port ISCT1_13
ISCT1_23: C_ISCT1_5.TNC(RF2) ; port ISCT1_23
ISCT1_ACC_Y: C_ISCT1_12.BNC(CH_1) ; port ISCT1_ACC_Y
ISCT1_DB9_1: C_ISCT1_7.D9M(Output) ; port ISCT1_DB9_1
ISCT1_DB9_2: C_ISCT1_7.D9M(B) ; port ISCT1_DB9_2
ISCT1_DB9_3: C_ISCT1_11.D9M(Output) ; port ISCT1_DB9_3
ISCT1_DB9_4: C_ISCT1_11.D9M(B) ; port ISCT1_DB9_4
ISCT1_XX: C_ISCT1_8.TNC(RF1) ; port ISCT1_XX
R4_ISCT1_1: C_ISCT1_9.TNC ; port R4_ISCT1_1
R4_ISCT1_2: C_ISCT1_9.TNC ; port R4_ISCT1_2
XX: C_ISCT1_12.3W3(Power) ; port XX

Not connected (* = marked no-connect by the designer): C_ISCT1_6 3W3(DC±17)* D9M(Output)*; C_ISCT1_7 D9F(Output)*; C_ISCT1_10 D15F(TEC)*; C_ISCT1_11 D9F(Output)*

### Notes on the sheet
- ISCT1 - Right Side
- Inside Enclosure
- labeled ISC_259, but label already used.
- ±18V from SUS-R1
- Gray cable, label 29. Need to relabel.
- Gray cable, label 30 Need to relabel.
- No Cable

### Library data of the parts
C_ISCT1_5 C_ISCT1_8 = Patch Panel Broadband PD: Patch Panel (D1200889); Serial: Sxxxxxxx; System: ISC
C_ISCT1_6 = Patch Panel DCPD Interface: Patch Panel (D1101072); Serial: Sxxxxxxx; System: ISC
C_ISCT1_7 C_ISCT1_11 = Patch Panel Uniblitz Shutters: Patch Panel (D1102369); Serial: Sxxxxxxx; System: ISC
C_ISCT1_9 = Patch Panel DCPD: Patch Panel (D1201399); Serial: Sxxxxxxx; System: ISC
C_ISCT1_10 = Patch Panel TEC Driver: Patch Panel (D1201483); Serial: Sxxxxxxx; System: ISC
C_ISCT1_12 = Patch Panel Analog Video: Patch Panel (D1102333); Serial: Sxxxxxxx; System: ISC

## Sheet IOT2_SH1.SchDoc: ISC System Wiring Diagram
size B; DrawnBy: Filiberto Clara; Engineer: Filiberto Clara; Organization: LIGO Laboratory; Address1: California Institute of Technology; Address2: Massachusetts Institute of Technology; DocumentNumber: D1900511; Revision: V11; SheetNumber: 26; SheetTotal: 39
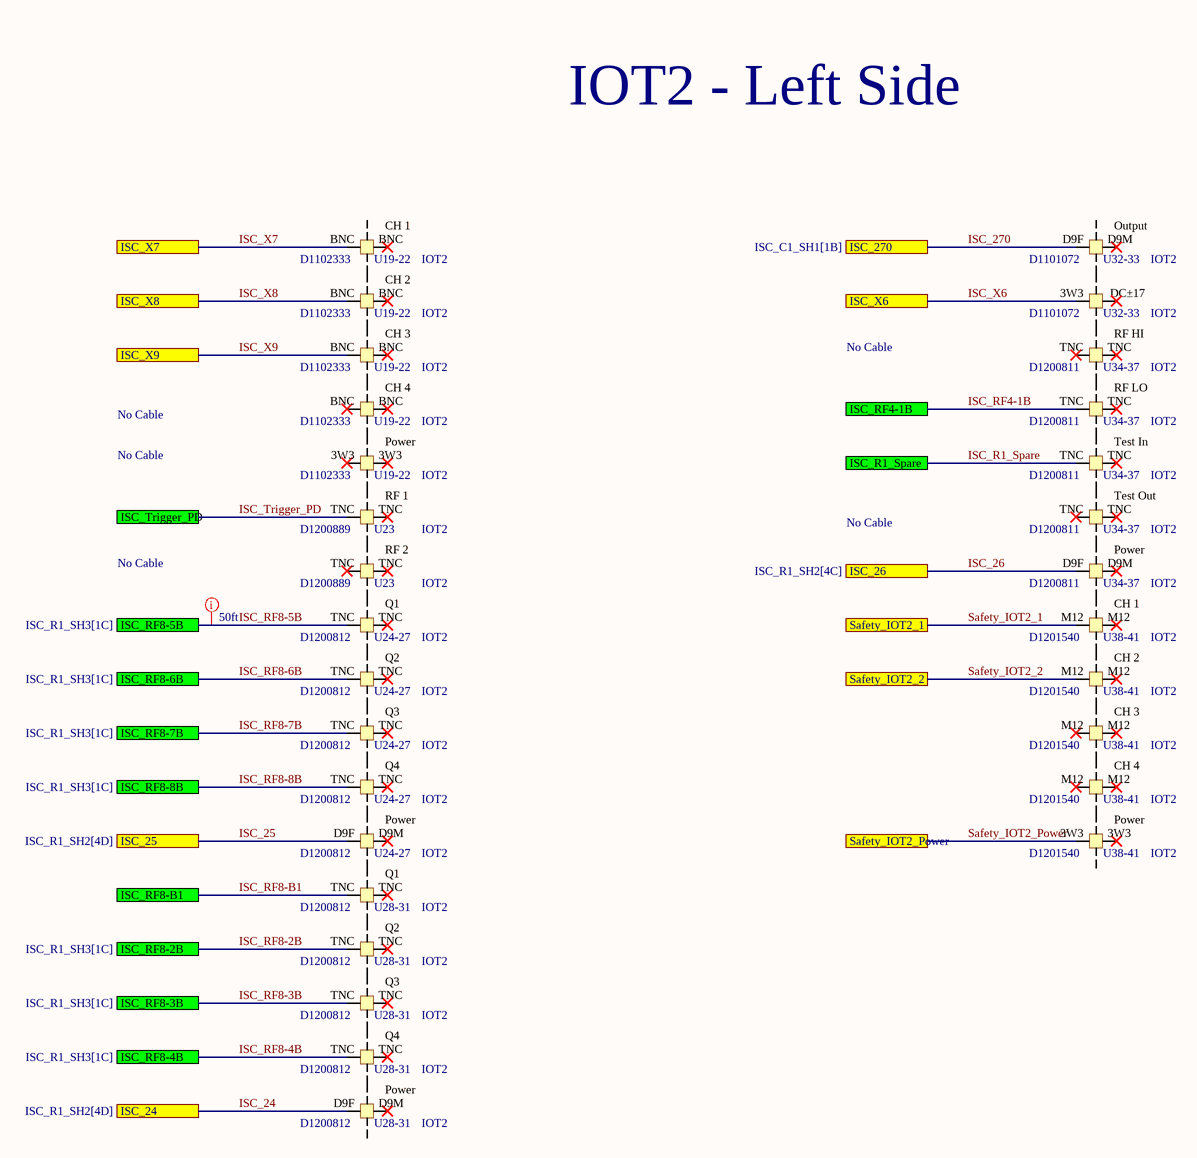
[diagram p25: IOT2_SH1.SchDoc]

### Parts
C_IOT2_1  DCC: D1102333  Rack: IOT2  Slot: U19-22  (hidden comment: Patch Panel Analog Video)  (parts A,B,C,D,E of 5)
C_IOT2_2  DCC: D1200889  Rack: IOT2  Slot: U23  (hidden comment: Patch Panel Broadband PD)  (parts A,B of 2)
C_IOT2_3  DCC: D1200812  Rack: IOT2  Slot: U24-27  (hidden comment: Patch Panel Single Frequency WFS RFPD)  (parts A,B,C,D,E of 5)
C_IOT2_4  DCC: D1200812  Rack: IOT2  Slot: U28-31  (hidden comment: Patch Panel Single Frequency WFS RFPD)  (parts A,B,C,D,E of 5)
C_IOT2_5  DCC: D1101072  Rack: IOT2  Slot: U32-33  (hidden comment: Patch Panel DCPD Interface)  (parts A,B of 2)
C_IOT2_6  DCC: D1200811  Rack: IOT2  Slot: U34-37  (hidden comment: Patch Panel Dual Frequency LSC RFPD)  (parts A,B,C,D,E of 5)
C_IOT2_7  DCC: D1201540  Rack: IOT2  Slot: U38-41  (hidden comment: Patch Panel Interlocks/Lighting)  (parts A,B,C,D,E of 5)

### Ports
ISC_24 (see ISC_R1_SH2[4D]), ISC_25 (see ISC_R1_SH2[4D]), ISC_26 (see ISC_R1_SH2[4C]), ISC_270 (see ISC_C1_SH1[1B]), ISC_R1_Spare, ISC_RF4-1B, ISC_RF8-2B (see ISC_R1_SH3[1C]), ISC_RF8-3B (see ISC_R1_SH3[1C]), ISC_RF8-4B (see ISC_R1_SH3[1C]), ISC_RF8-5B (see ISC_R1_SH3[1C]), ISC_RF8-6B (see ISC_R1_SH3[1C]), ISC_RF8-7B (see ISC_R1_SH3[1C]), ISC_RF8-8B (see ISC_R1_SH3[1C]), ISC_RF8-B1, ISC_Trigger_PD, ISC_X6, ISC_X7, ISC_X8, ISC_X9, Safety_IOT2_1, Safety_IOT2_2, Safety_IOT2_Power

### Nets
ISC_24: C_IOT2_4.D9F(Power) ; port ISC_24
ISC_25: C_IOT2_3.D9F(Power) ; port ISC_25
ISC_26: C_IOT2_6.D9F(Power) ; port ISC_26
ISC_270: C_IOT2_5.D9F(Output) ; port ISC_270
ISC_R1_Spare: C_IOT2_6.TNC(TestIn) ; port ISC_R1_Spare
ISC_RF4-1B: C_IOT2_6.TNC(RFHI) ; port ISC_RF4-1B
ISC_RF8-2B: C_IOT2_4.TNC(RFLO) ; port ISC_RF8-2B
ISC_RF8-3B: C_IOT2_4.TNC(TestIn) ; port ISC_RF8-3B
ISC_RF8-4B: C_IOT2_4.TNC(TestOut) ; port ISC_RF8-4B
ISC_RF8-5B: C_IOT2_3.TNC(RFHI) ; port ISC_RF8-5B
ISC_RF8-6B: C_IOT2_3.TNC(RFLO) ; port ISC_RF8-6B
ISC_RF8-7B: C_IOT2_3.TNC(TestIn) ; port ISC_RF8-7B
ISC_RF8-8B: C_IOT2_3.TNC(TestOut) ; port ISC_RF8-8B
ISC_RF8-B1: C_IOT2_4.TNC(RFHI) ; port ISC_RF8-B1
ISC_Trigger_PD: C_IOT2_2.TNC(RF1) ; port ISC_Trigger_PD
ISC_X6: C_IOT2_5.3W3(DC±17) ; port ISC_X6
ISC_X7: C_IOT2_1.BNC(CH_1) ; port ISC_X7
ISC_X8: C_IOT2_1.BNC(CH_2) ; port ISC_X8
ISC_X9: C_IOT2_1.BNC(CH_3) ; port ISC_X9
Safety_IOT2_1: C_IOT2_7.M12(CH_1) ; port Safety_IOT2_1
Safety_IOT2_2: C_IOT2_7.M12(CH_2) ; port Safety_IOT2_2
Safety_IOT2_Power: C_IOT2_7.3W3(Power) ; port Safety_IOT2_Power

Not connected (* = marked no-connect by the designer): C_IOT2_1 3W3(Power)*; C_IOT2_3 D9M(Power)*; C_IOT2_4 D9M(Power)*; C_IOT2_5 D9M(Output)*; C_IOT2_6 D9M(Power)*

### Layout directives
Length: 50ft: ISC_RF8-5B

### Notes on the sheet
- IOT2 - Left Side
- No Cable

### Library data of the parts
C_IOT2_1 = Patch Panel Analog Video: as C_ISCT1_12 on sheet ISCT1_SH2
C_IOT2_2 = Patch Panel Broadband PD: as C_ISCT1_5 on sheet ISCT1_SH2
C_IOT2_3 C_IOT2_4 = Patch Panel Single Frequency WFS RFPD: Patch Panel (D1200812); Serial: Sxxxxxxx; System: ISC
C_IOT2_5 = Patch Panel DCPD Interface: as C_ISCT1_6 on sheet ISCT1_SH2
C_IOT2_6 = Patch Panel Dual Frequency LSC RFPD: as C_ISCT1_1 on sheet ISCT1_SH1
C_IOT2_7 = Patch Panel Interlocks/Lighting: Patch Panel Interlocks/Lighting (D1201540); Serial: Sxxxxxxx; System: ISC

## Sheet IOT2_SH2.SchDoc: ISC System Wiring Diagram
size B; DrawnBy: Filiberto Clara; Engineer: Filiberto Clara; Organization: LIGO Laboratory; Address1: California Institute of Technology; Address2: Massachusetts Institute of Technology; DocumentNumber: D1900511; Revision: V11; SheetNumber: 27; SheetTotal: 39
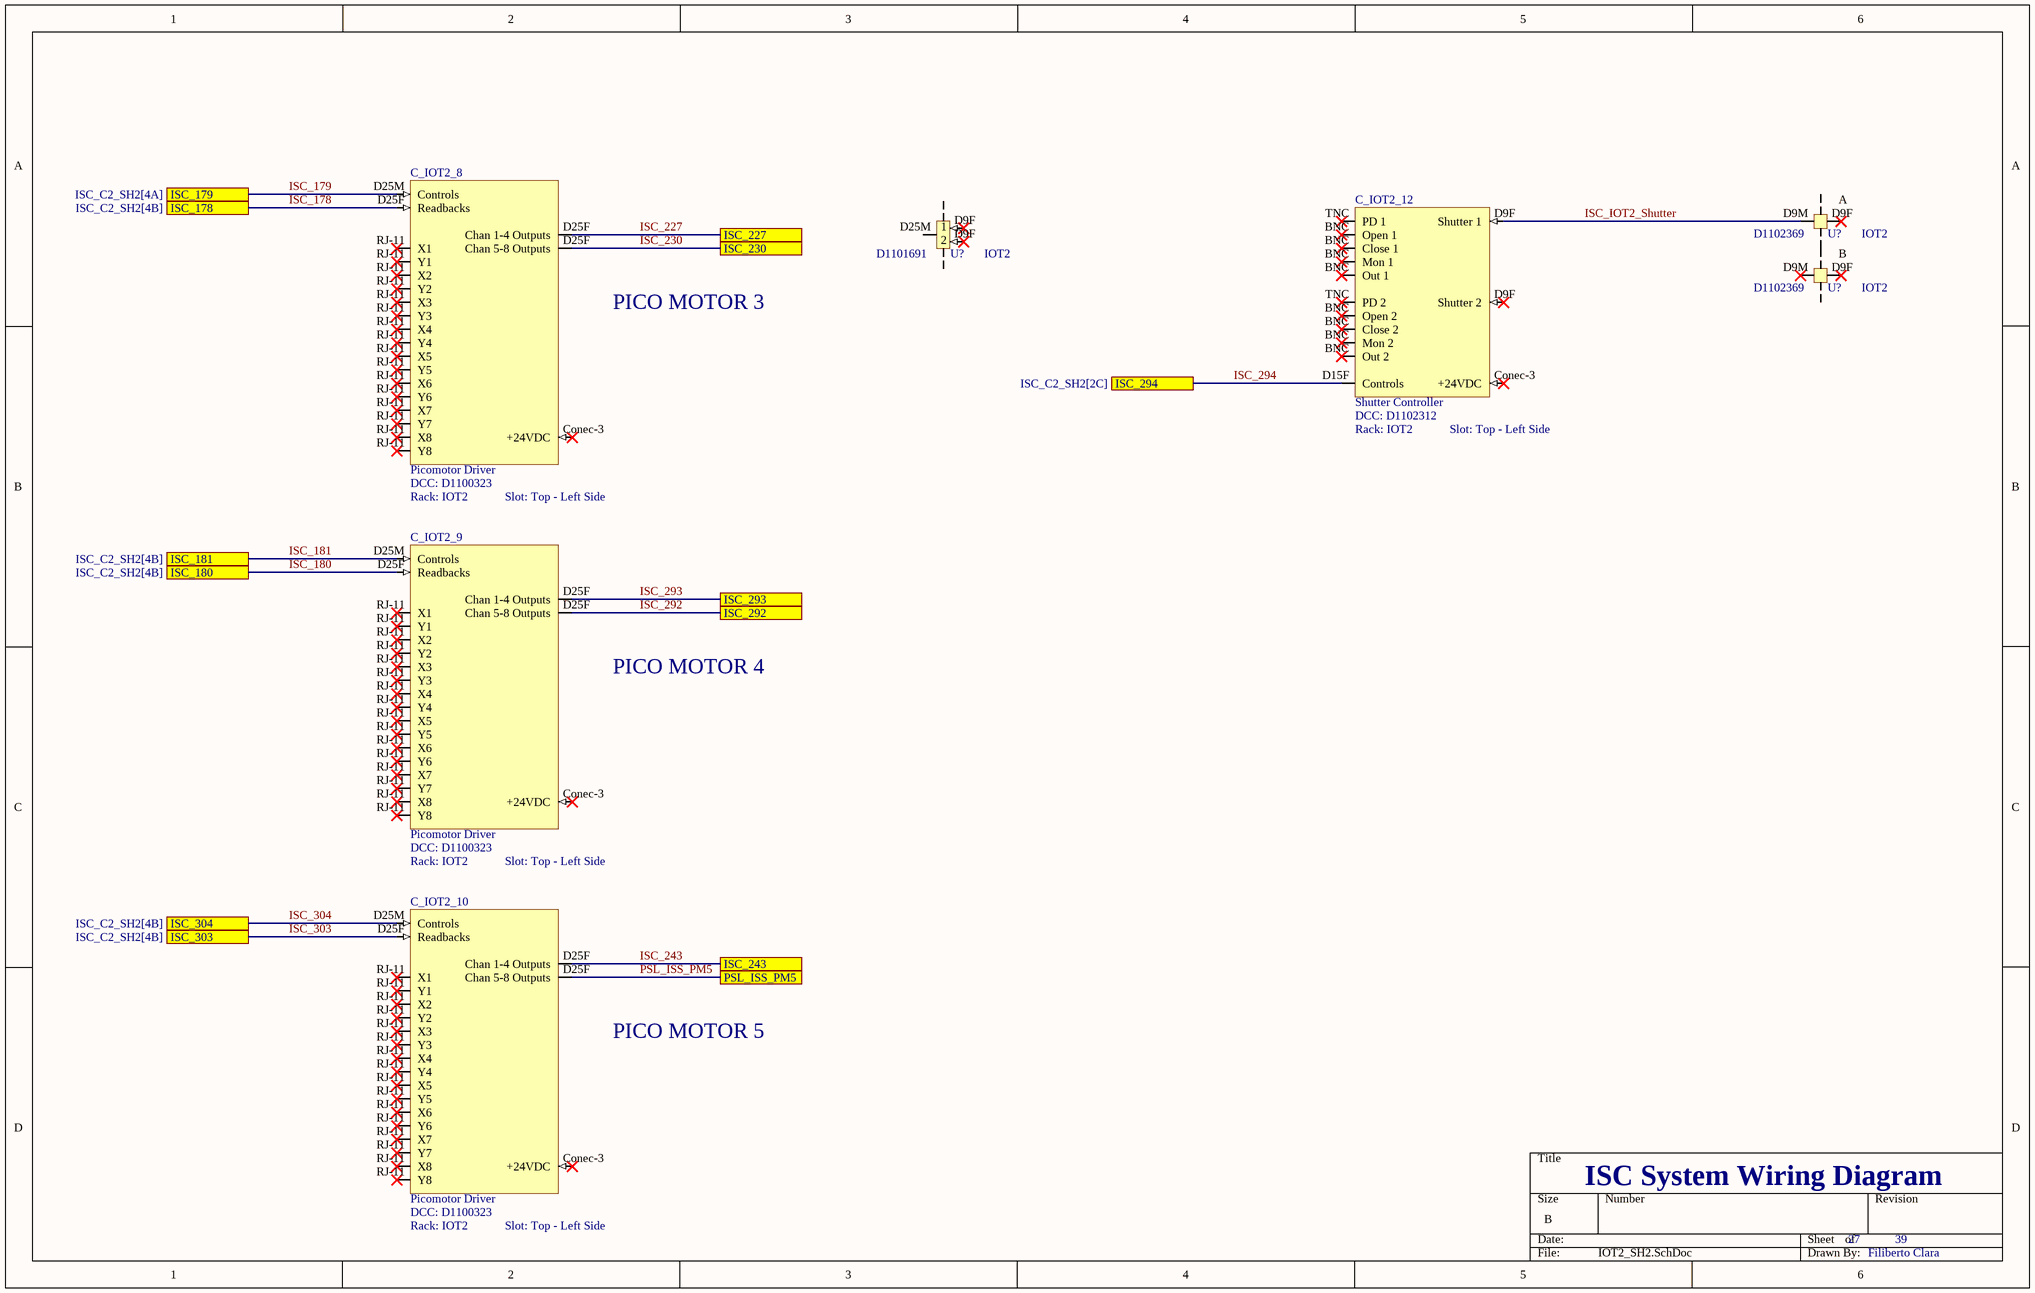
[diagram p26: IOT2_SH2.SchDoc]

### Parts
C_IOT2_8  Picomotor Driver  DCC: D1100323  Rack: IOT2  Slot: Top - Left Side
C_IOT2_9  Picomotor Driver  DCC: D1100323  Rack: IOT2  Slot: Top - Left Side
C_IOT2_10  Picomotor Driver  DCC: D1100323  Rack: IOT2  Slot: Top - Left Side
C_IOT2_11  DCC: D1101691  Rack: IOT2  Slot: U?  (hidden comment: Patch Panel Picomotor Breakout)
C_IOT2_12  Shutter Controller  DCC: D1102312  Rack: IOT2  Slot: Top - Left Side
C_IOT2_13  DCC: D1102369  Rack: IOT2  Slot: U?  (hidden comment: Patch Panel Uniblitz Shutters)  (parts A,B of 2)

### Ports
ISC_178 (see ISC_C2_SH2[4B]), ISC_179 (see ISC_C2_SH2[4A]), ISC_180 (see ISC_C2_SH2[4B]), ISC_181 (see ISC_C2_SH2[4B]), ISC_227, ISC_230, ISC_243, ISC_292, ISC_293, ISC_294 (see ISC_C2_SH2[2C]), ISC_303 (see ISC_C2_SH2[4B]), ISC_304 (see ISC_C2_SH2[4B]), PSL_ISS_PM5

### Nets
ISC_178: C_IOT2_8.D25F(Readbacks) ; port ISC_178
ISC_179: C_IOT2_8.D25M(Controls) ; port ISC_179
ISC_180: C_IOT2_9.D25F(Readbacks) ; port ISC_180
ISC_181: C_IOT2_9.D25M(Controls) ; port ISC_181
ISC_227: C_IOT2_8.D25F(Chan_1-4_Outputs) ; port ISC_227
ISC_230: C_IOT2_8.D25F(Chan_5-8_Outputs) ; port ISC_230
ISC_243: C_IOT2_10.D25F(Chan_1-4_Outputs) ; port ISC_243
ISC_292: C_IOT2_9.D25F(Chan_5-8_Outputs) ; port ISC_292
ISC_293: C_IOT2_9.D25F(Chan_1-4_Outputs) ; port ISC_293
ISC_294: C_IOT2_12.D15F(Controls) ; port ISC_294
ISC_303: C_IOT2_10.D25F(Readbacks) ; port ISC_303
ISC_304: C_IOT2_10.D25M(Controls) ; port ISC_304
ISC_IOT2_Shutter: C_IOT2_12.D9F(Shutter_1) C_IOT2_13.D9M(Output)
PSL_ISS_PM5: C_IOT2_10.D25F(Chan_5-8_Outputs) ; port PSL_ISS_PM5

Not connected (* = marked no-connect by the designer): C_IOT2_8 Conec-3(+24VDC)* RJ-11(X1)*; C_IOT2_9 Conec-3(+24VDC)* RJ-11(X1)*; C_IOT2_10 Conec-3(+24VDC)* RJ-11(X1)*; C_IOT2_11 D9F(2)* D25M(Pico); C_IOT2_12 BNC(Open_1)* Conec-3(+24VDC)* TNC(PD_1)*; C_IOT2_13 D9F(Output)*

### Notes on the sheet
- PICO MOTOR 3
- PICO MOTOR 4
- PICO MOTOR 5

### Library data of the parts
C_IOT2_8-C_IOT2_10 = Picomotor Driver: Serial: Sxxxxxxx; System: ISC
C_IOT2_11 = Patch Panel Picomotor Breakout: Patch Panel (D1101691); Serial: Sxxxxxxx; System: ISC
C_IOT2_12 = Shutter Controller: Serial: Sxxxxxxx; System: ISC
C_IOT2_13 = Patch Panel Uniblitz Shutters: as C_ISCT1_7 on sheet ISCT1_SH2

## Sheet HAM6_SH1.SchDoc: ISC System Wiring Diagram
size B; DrawnBy: Filiberto Clara; Engineer: Filiberto Clara; Organization: LIGO Laboratory; Address1: California Institute of Technology; Address2: Massachusetts Institute of Technology; DocumentNumber: D1900511; Revision: V11; SheetNumber: 28; SheetTotal: 39
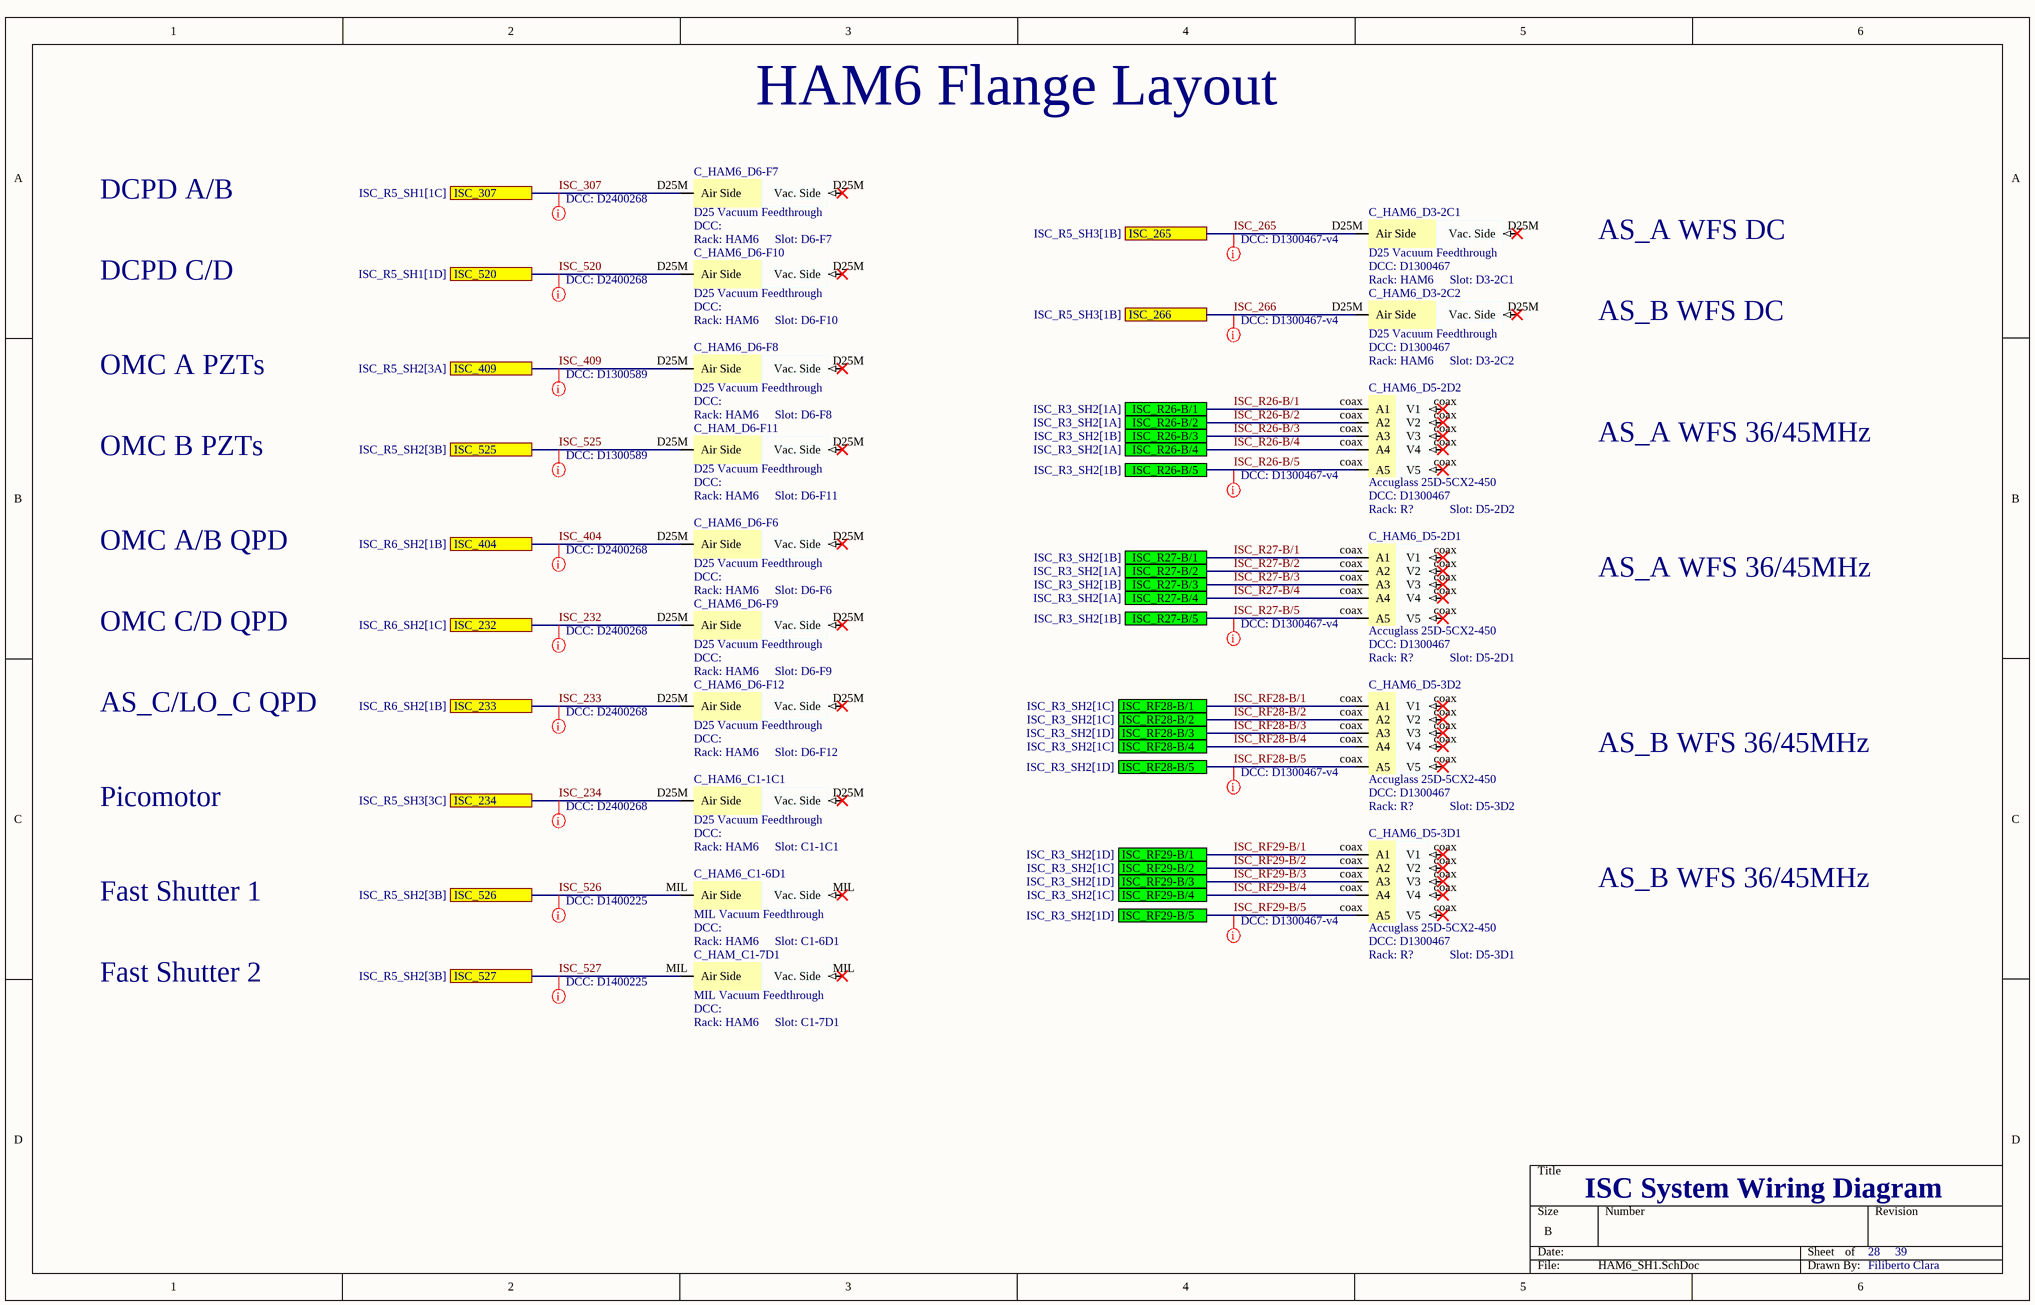
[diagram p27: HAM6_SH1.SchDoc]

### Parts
C_HAM6_C1-1C1  D25 Vacuum Feedthrough  Rack: HAM6  Slot: C1-1C1
C_HAM6_C1-6D1  MIL Vacuum Feedthrough  Rack: HAM6  Slot: C1-6D1
C_HAM6_D3-2C1  D25 Vacuum Feedthrough  DCC: D1300467  Rack: HAM6  Slot: D3-2C1
C_HAM6_D3-2C2  D25 Vacuum Feedthrough  DCC: D1300467  Rack: HAM6  Slot: D3-2C2
C_HAM6_D5-2D1  Accuglass 25D-5CX2-450  DCC: D1300467  Rack: R?  Slot: D5-2D1
C_HAM6_D5-2D2  Accuglass 25D-5CX2-450  DCC: D1300467  Rack: R?  Slot: D5-2D2
C_HAM6_D5-3D1  Accuglass 25D-5CX2-450  DCC: D1300467  Rack: R?  Slot: D5-3D1
C_HAM6_D5-3D2  Accuglass 25D-5CX2-450  DCC: D1300467  Rack: R?  Slot: D5-3D2
C_HAM6_D6-F6  D25 Vacuum Feedthrough  Rack: HAM6  Slot: D6-F6
C_HAM6_D6-F7  D25 Vacuum Feedthrough  Rack: HAM6  Slot: D6-F7
C_HAM6_D6-F8  D25 Vacuum Feedthrough  Rack: HAM6  Slot: D6-F8
C_HAM6_D6-F9  D25 Vacuum Feedthrough  Rack: HAM6  Slot: D6-F9
C_HAM6_D6-F10  D25 Vacuum Feedthrough  Rack: HAM6  Slot: D6-F10
C_HAM6_D6-F12  D25 Vacuum Feedthrough  Rack: HAM6  Slot: D6-F12
C_HAM_C1-7D1  MIL Vacuum Feedthrough  Rack: HAM6  Slot: C1-7D1
C_HAM_D6-F11  D25 Vacuum Feedthrough  Rack: HAM6  Slot: D6-F11

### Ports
ISC_232 (see ISC_R6_SH2[1C]), ISC_233 (see ISC_R6_SH2[1B]), ISC_234 (see ISC_R5_SH3[3C]), ISC_265 (see ISC_R5_SH3[1B]), ISC_266 (see ISC_R5_SH3[1B]), ISC_307 (see ISC_R5_SH1[1C]), ISC_404 (see ISC_R6_SH2[1B]), ISC_409 (see ISC_R5_SH2[3A]), ISC_520 (see ISC_R5_SH1[1D]), ISC_525 (see ISC_R5_SH2[3B]), ISC_526 (see ISC_R5_SH2[3B]), ISC_527 (see ISC_R5_SH2[3B]), ISC_R26-B/1 (see ISC_R3_SH2[1A]), ISC_R26-B/2 (see ISC_R3_SH2[1A]), ISC_R26-B/3 (see ISC_R3_SH2[1B]), ISC_R26-B/4 (see ISC_R3_SH2[1A]), ISC_R26-B/5 (see ISC_R3_SH2[1B]), ISC_R27-B/1 (see ISC_R3_SH2[1B]), ISC_R27-B/2 (see ISC_R3_SH2[1A]), ISC_R27-B/3 (see ISC_R3_SH2[1B]), ISC_R27-B/4 (see ISC_R3_SH2[1A]), ISC_R27-B/5 (see ISC_R3_SH2[1B]), ISC_RF28-B/1 (see ISC_R3_SH2[1C]), ISC_RF28-B/2 (see ISC_R3_SH2[1C]), ISC_RF28-B/3 (see ISC_R3_SH2[1D]), ISC_RF28-B/4 (see ISC_R3_SH2[1C]), ISC_RF28-B/5 (see ISC_R3_SH2[1D]), ISC_RF29-B/1 (see ISC_R3_SH2[1D]), ISC_RF29-B/2 (see ISC_R3_SH2[1C]), ISC_RF29-B/3 (see ISC_R3_SH2[1D]), ISC_RF29-B/4 (see ISC_R3_SH2[1C]), ISC_RF29-B/5 (see ISC_R3_SH2[1D])

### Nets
ISC_232: C_HAM6_D6-F9.D25M(Vac._Side) ; port ISC_232
ISC_233: C_HAM6_D6-F12.D25M(Vac._Side) ; port ISC_233
ISC_234: C_HAM6_C1-1C1.D25M(Vac._Side) ; port ISC_234
ISC_265: C_HAM6_D3-2C1.D25M(Vac._Side) ; port ISC_265
ISC_266: C_HAM6_D3-2C2.D25M(Vac._Side) ; port ISC_266
ISC_307: C_HAM6_D6-F7.D25M(Vac._Side) ; port ISC_307
ISC_404: C_HAM6_D6-F6.D25M(Vac._Side) ; port ISC_404
ISC_409: C_HAM6_D6-F8.D25M(Vac._Side) ; port ISC_409
ISC_520: C_HAM6_D6-F10.D25M(Vac._Side) ; port ISC_520
ISC_525: C_HAM_D6-F11.D25M(Vac._Side) ; port ISC_525
ISC_526: C_HAM6_C1-6D1.MIL(Vac._Side) ; port ISC_526
ISC_527: C_HAM_C1-7D1.MIL(Vac._Side) ; port ISC_527
ISC_R26-B/1: C_HAM6_D5-2D2.coax(V1) ; port ISC_R26-B/1
ISC_R26-B/2: C_HAM6_D5-2D2.coax(A2) ; port ISC_R26-B/2
ISC_R26-B/3: C_HAM6_D5-2D2.coax(A3) ; port ISC_R26-B/3
ISC_R26-B/4: C_HAM6_D5-2D2.coax(A4) ; port ISC_R26-B/4
ISC_R26-B/5: C_HAM6_D5-2D2.coax(A5) ; port ISC_R26-B/5
ISC_R27-B/1: C_HAM6_D5-2D1.coax(V1) ; port ISC_R27-B/1
ISC_R27-B/2: C_HAM6_D5-2D1.coax(A2) ; port ISC_R27-B/2
ISC_R27-B/3: C_HAM6_D5-2D1.coax(A3) ; port ISC_R27-B/3
ISC_R27-B/4: C_HAM6_D5-2D1.coax(A4) ; port ISC_R27-B/4
ISC_R27-B/5: C_HAM6_D5-2D1.coax(A5) ; port ISC_R27-B/5
ISC_RF28-B/1: C_HAM6_D5-3D2.coax(V1) ; port ISC_RF28-B/1
ISC_RF28-B/2: C_HAM6_D5-3D2.coax(A2) ; port ISC_RF28-B/2
ISC_RF28-B/3: C_HAM6_D5-3D2.coax(A3) ; port ISC_RF28-B/3
ISC_RF28-B/4: C_HAM6_D5-3D2.coax(A4) ; port ISC_RF28-B/4
ISC_RF28-B/5: C_HAM6_D5-3D2.coax(A5) ; port ISC_RF28-B/5
ISC_RF29-B/1: C_HAM6_D5-3D1.coax(V1) ; port ISC_RF29-B/1
ISC_RF29-B/2: C_HAM6_D5-3D1.coax(A2) ; port ISC_RF29-B/2
ISC_RF29-B/3: C_HAM6_D5-3D1.coax(A3) ; port ISC_RF29-B/3
ISC_RF29-B/4: C_HAM6_D5-3D1.coax(A4) ; port ISC_RF29-B/4
ISC_RF29-B/5: C_HAM6_D5-3D1.coax(A5) ; port ISC_RF29-B/5

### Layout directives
DCC: D1300467-v4: ISC_265, ISC_266, ISC_R26-B/5, ISC_R27-B/5, ISC_RF28-B/5, ISC_RF29-B/5
DCC: D2400268: ISC_232, ISC_233, ISC_234, ISC_307, ISC_404, ISC_520
DCC: D1300589: ISC_409, ISC_525
DCC: D1400225: ISC_526, ISC_527

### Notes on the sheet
- HAM6 Flange Layout
- DCPD A/B
- AS_A WFS DC
- DCPD C/D
- OMC A PZTs
- AS_B WFS DC
- AS_A WFS 36/45MHz
- OMC B PZTs
- OMC A/B QPD
- OMC C/D QPD
- AS_C/LO_C QPD
- AS_B WFS 36/45MHz
- Picomotor
- Fast Shutter 1
- Fast Shutter 2

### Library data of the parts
C_HAM6_C1-1C1 C_HAM6_C1-6D1 C_HAM6_D3-2C1 C_HAM6_D3-2C2 C_HAM6_D6-F6-C_HAM6_D6-F10 C_HAM6_D6-F12 C_HAM_C1-7D1 C_HAM_D6-F11 = VacFeedD25: Serial: Sxxxxxxx; System: ISC
C_HAM6_D5-2D1 C_HAM6_D5-2D2 C_HAM6_D5-3D1 C_HAM6_D5-3D2 = Vac.Feed Coax DB 5W5: Vac.Feed Coax Dsub DB5W5; System: ISC

## Sheet HAM6_SH2.SchDoc: ISC System Wiring Diagram
size B; DrawnBy: Filiberto Clara; Engineer: Filiberto Clara; Organization: LIGO Laboratory; Address1: California Institute of Technology; Address2: Massachusetts Institute of Technology; DocumentNumber: D1900511; Revision: V11; SheetNumber: 29; SheetTotal: 39
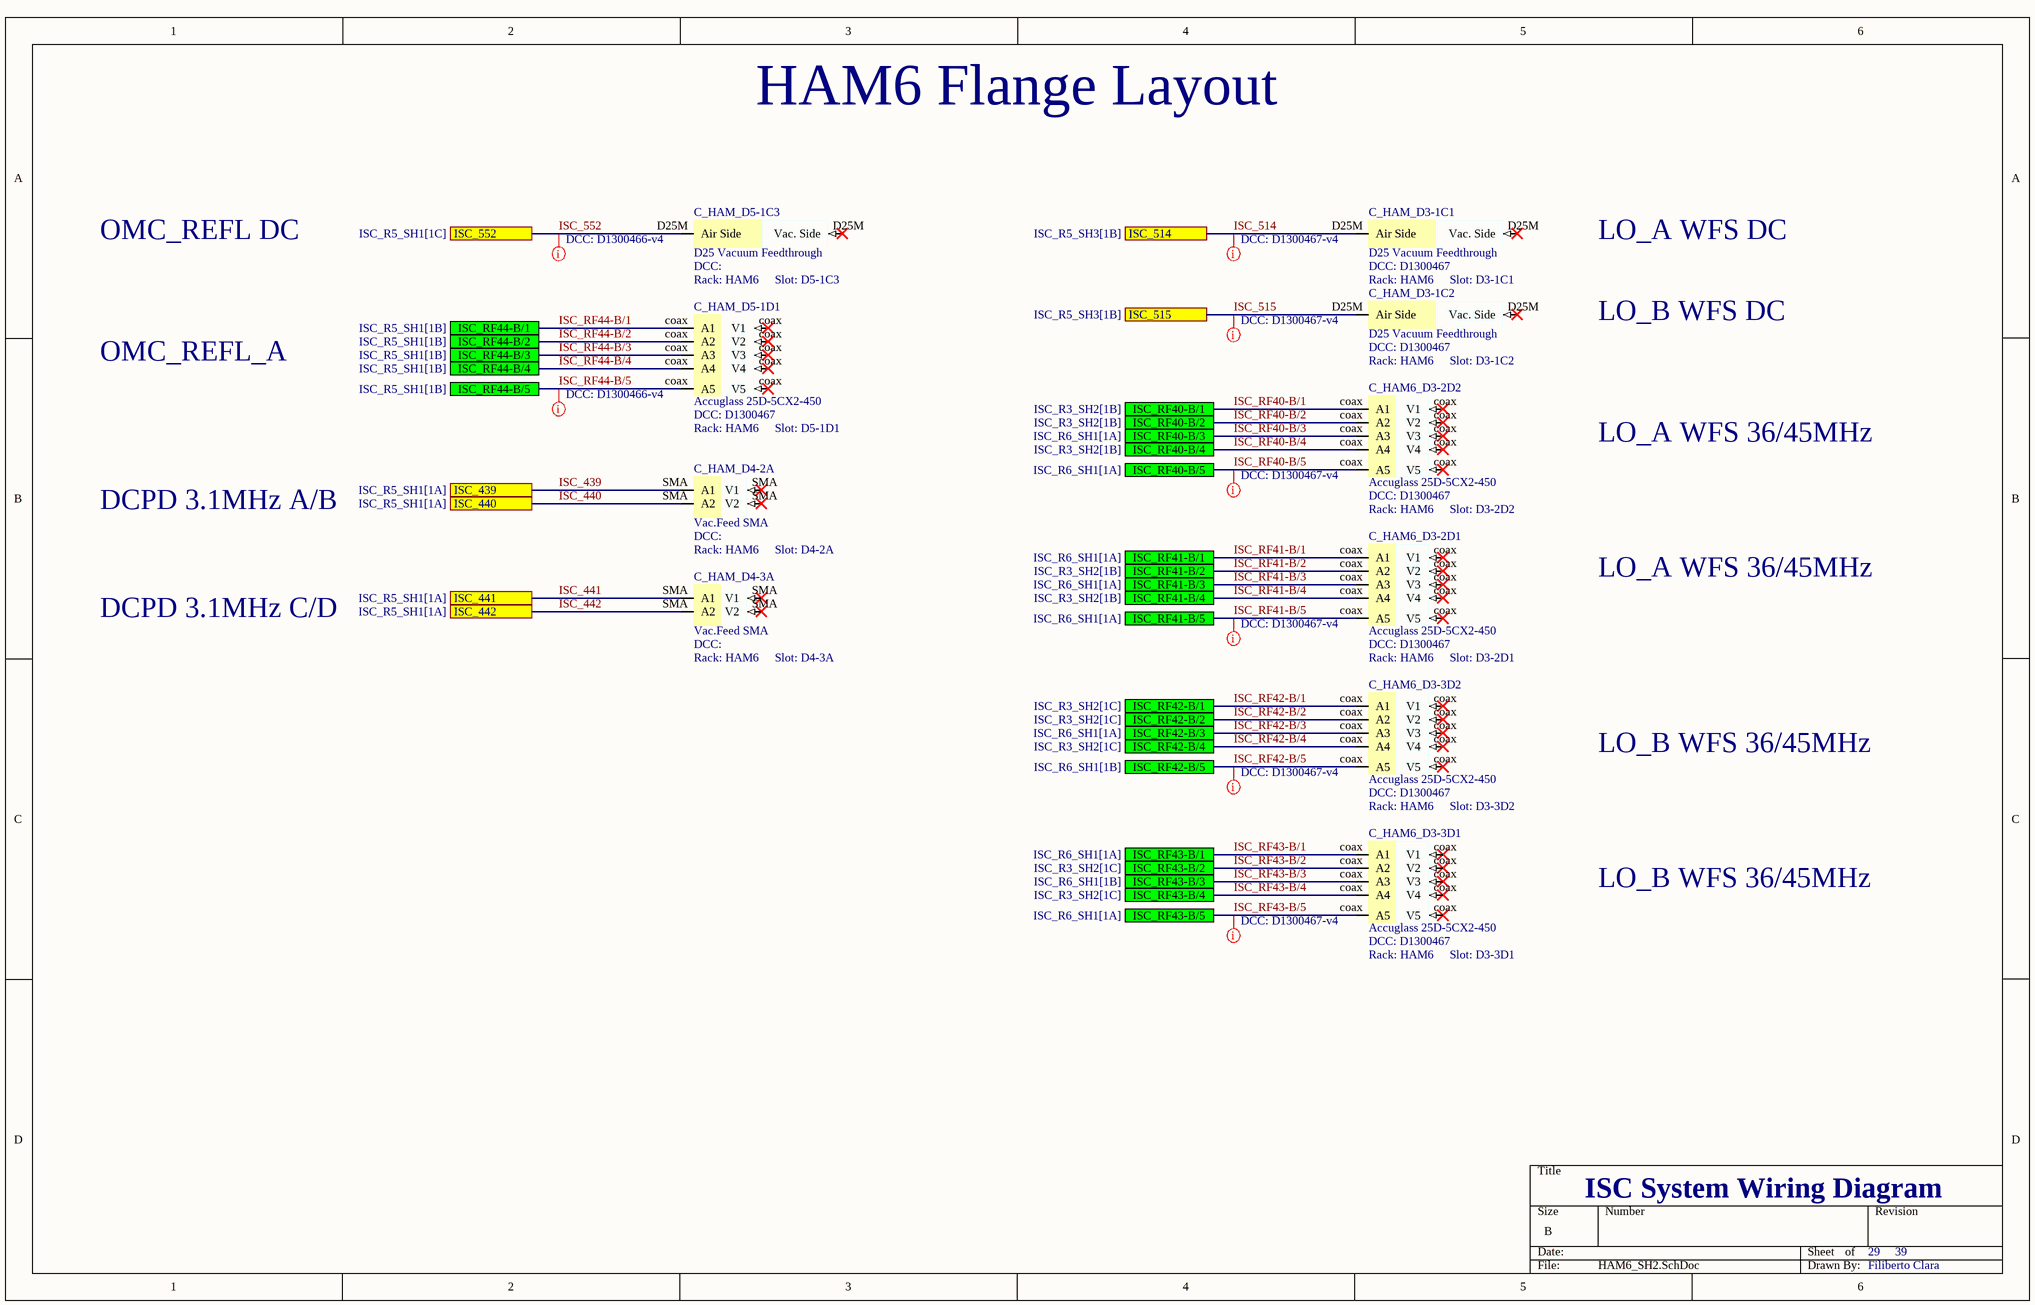
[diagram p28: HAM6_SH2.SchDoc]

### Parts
C_HAM6_D3-2D1  Accuglass 25D-5CX2-450  DCC: D1300467  Rack: HAM6  Slot: D3-2D1
C_HAM6_D3-2D2  Accuglass 25D-5CX2-450  DCC: D1300467  Rack: HAM6  Slot: D3-2D2
C_HAM6_D3-3D1  Accuglass 25D-5CX2-450  DCC: D1300467  Rack: HAM6  Slot: D3-3D1
C_HAM6_D3-3D2  Accuglass 25D-5CX2-450  DCC: D1300467  Rack: HAM6  Slot: D3-3D2
C_HAM_D3-1C1  D25 Vacuum Feedthrough  DCC: D1300467  Rack: HAM6  Slot: D3-1C1
C_HAM_D3-1C2  D25 Vacuum Feedthrough  DCC: D1300467  Rack: HAM6  Slot: D3-1C2
C_HAM_D4-2A  Vac.Feed SMA  Rack: HAM6  Slot: D4-2A
C_HAM_D4-3A  Vac.Feed SMA  Rack: HAM6  Slot: D4-3A
C_HAM_D5-1C3  D25 Vacuum Feedthrough  Rack: HAM6  Slot: D5-1C3
C_HAM_D5-1D1  Accuglass 25D-5CX2-450  DCC: D1300467  Rack: HAM6  Slot: D5-1D1

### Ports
ISC_439 (see ISC_R5_SH1[1A]), ISC_440 (see ISC_R5_SH1[1A]), ISC_441 (see ISC_R5_SH1[1A]), ISC_442 (see ISC_R5_SH1[1A]), ISC_514 (see ISC_R5_SH3[1B]), ISC_515 (see ISC_R5_SH3[1B]), ISC_552 (see ISC_R5_SH1[1C]), ISC_RF40-B/1 (see ISC_R3_SH2[1B]), ISC_RF40-B/2 (see ISC_R3_SH2[1B]), ISC_RF40-B/3 (see ISC_R6_SH1[1A]), ISC_RF40-B/4 (see ISC_R3_SH2[1B]), ISC_RF40-B/5 (see ISC_R6_SH1[1A]), ISC_RF41-B/1 (see ISC_R6_SH1[1A]), ISC_RF41-B/2 (see ISC_R3_SH2[1B]), ISC_RF41-B/3 (see ISC_R6_SH1[1A]), ISC_RF41-B/4 (see ISC_R3_SH2[1B]), ISC_RF41-B/5 (see ISC_R6_SH1[1A]), ISC_RF42-B/1 (see ISC_R3_SH2[1C]), ISC_RF42-B/2 (see ISC_R3_SH2[1C]), ISC_RF42-B/3 (see ISC_R6_SH1[1A]), ISC_RF42-B/4 (see ISC_R3_SH2[1C]), ISC_RF42-B/5 (see ISC_R6_SH1[1B]), ISC_RF43-B/1 (see ISC_R6_SH1[1A]), ISC_RF43-B/2 (see ISC_R3_SH2[1C]), ISC_RF43-B/3 (see ISC_R6_SH1[1B]), ISC_RF43-B/4 (see ISC_R3_SH2[1C]), ISC_RF43-B/5 (see ISC_R6_SH1[1A]), ISC_RF44-B/1 (see ISC_R5_SH1[1B]), ISC_RF44-B/2 (see ISC_R5_SH1[1B]), ISC_RF44-B/3 (see ISC_R5_SH1[1B]), ISC_RF44-B/4 (see ISC_R5_SH1[1B]), ISC_RF44-B/5 (see ISC_R5_SH1[1B])

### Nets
ISC_439: C_HAM_D4-2A.SMA(A1) ; port ISC_439
ISC_440: C_HAM_D4-2A.SMA(A2) ; port ISC_440
ISC_441: C_HAM_D4-3A.SMA(A1) ; port ISC_441
ISC_442: C_HAM_D4-3A.SMA(A2) ; port ISC_442
ISC_514: C_HAM_D3-1C1.D25M(Vac._Side) ; port ISC_514
ISC_515: C_HAM_D3-1C2.D25M(Vac._Side) ; port ISC_515
ISC_552: C_HAM_D5-1C3.D25M(Vac._Side) ; port ISC_552
ISC_RF40-B/1: C_HAM6_D3-2D2.coax(V1) ; port ISC_RF40-B/1
ISC_RF40-B/2: C_HAM6_D3-2D2.coax(A2) ; port ISC_RF40-B/2
ISC_RF40-B/3: C_HAM6_D3-2D2.coax(A3) ; port ISC_RF40-B/3
ISC_RF40-B/4: C_HAM6_D3-2D2.coax(A4) ; port ISC_RF40-B/4
ISC_RF40-B/5: C_HAM6_D3-2D2.coax(A5) ; port ISC_RF40-B/5
ISC_RF41-B/1: C_HAM6_D3-2D1.coax(V1) ; port ISC_RF41-B/1
ISC_RF41-B/2: C_HAM6_D3-2D1.coax(A2) ; port ISC_RF41-B/2
ISC_RF41-B/3: C_HAM6_D3-2D1.coax(A3) ; port ISC_RF41-B/3
ISC_RF41-B/4: C_HAM6_D3-2D1.coax(A4) ; port ISC_RF41-B/4
ISC_RF41-B/5: C_HAM6_D3-2D1.coax(A5) ; port ISC_RF41-B/5
ISC_RF42-B/1: C_HAM6_D3-3D2.coax(V1) ; port ISC_RF42-B/1
ISC_RF42-B/2: C_HAM6_D3-3D2.coax(A2) ; port ISC_RF42-B/2
ISC_RF42-B/3: C_HAM6_D3-3D2.coax(A3) ; port ISC_RF42-B/3
ISC_RF42-B/4: C_HAM6_D3-3D2.coax(A4) ; port ISC_RF42-B/4
ISC_RF42-B/5: C_HAM6_D3-3D2.coax(A5) ; port ISC_RF42-B/5
ISC_RF43-B/1: C_HAM6_D3-3D1.coax(V1) ; port ISC_RF43-B/1
ISC_RF43-B/2: C_HAM6_D3-3D1.coax(A2) ; port ISC_RF43-B/2
ISC_RF43-B/3: C_HAM6_D3-3D1.coax(A3) ; port ISC_RF43-B/3
ISC_RF43-B/4: C_HAM6_D3-3D1.coax(A4) ; port ISC_RF43-B/4
ISC_RF43-B/5: C_HAM6_D3-3D1.coax(A5) ; port ISC_RF43-B/5
ISC_RF44-B/1: C_HAM_D5-1D1.coax(V1) ; port ISC_RF44-B/1
ISC_RF44-B/2: C_HAM_D5-1D1.coax(A2) ; port ISC_RF44-B/2
ISC_RF44-B/3: C_HAM_D5-1D1.coax(A3) ; port ISC_RF44-B/3
ISC_RF44-B/4: C_HAM_D5-1D1.coax(A4) ; port ISC_RF44-B/4
ISC_RF44-B/5: C_HAM_D5-1D1.coax(A5) ; port ISC_RF44-B/5

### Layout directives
DCC: D1300467-v4: ISC_514, ISC_515, ISC_RF40-B/5, ISC_RF41-B/5, ISC_RF42-B/5, ISC_RF43-B/5
DCC: D1300466-v4: ISC_552, ISC_RF44-B/5

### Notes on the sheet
- HAM6 Flange Layout
- OMC_REFL DC
- LO_A WFS DC
- OMC_REFL_A
- LO_B WFS DC
- LO_A WFS 36/45MHz
- DCPD 3.1MHz A/B
- DCPD 3.1MHz C/D
- LO_B WFS 36/45MHz

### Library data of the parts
C_HAM6_D3-2D1 C_HAM6_D3-2D2 C_HAM6_D3-3D1 C_HAM6_D3-3D2 C_HAM_D5-1D1 = Vac.Feed Coax DB 5W5: Vac.Feed Coax Dsub DB5W5; System: ISC
C_HAM_D3-1C1 C_HAM_D3-1C2 C_HAM_D5-1C3 = VacFeedD25: Serial: Sxxxxxxx; System: ISC
C_HAM_D4-2A C_HAM_D4-3A = Vac.Feed SMA: Vac.Feed coax SMA; Serial: Sxxxxxxx; System: ISC

## Sheet SqueezerWfsWiring.SchDoc: Squeezer Wavefront Sensing
size B; Organization: LIGO Laboratory; Address1: California Institute of Technology; Address2: Massachusetts Institute of Technology; DocumentNumber: D1900511; Revision: V11; SheetNumber: 30; SheetTotal: 39; DrawnBy: R.  Abbott; Engineer: R.  Abbott; PageSetup: Record=PageOptions¦CenterHorizontal=True¦CenterVertical=True¦PrintScale=1.09¦XCorrection=1.00¦YCorrection=1.00¦PrintKind=0¦BorderSize=5000000¦LeftOffset=0¦BottomOffset=0¦Orientation=2¦PaperLength=1000¦PaperWidth=1000¦Scale=100¦PaperSource=7¦PrintQuality=-4¦MediaType=1¦DitherType=10¦PaperKind=11x17¦PrintScaleMode=1
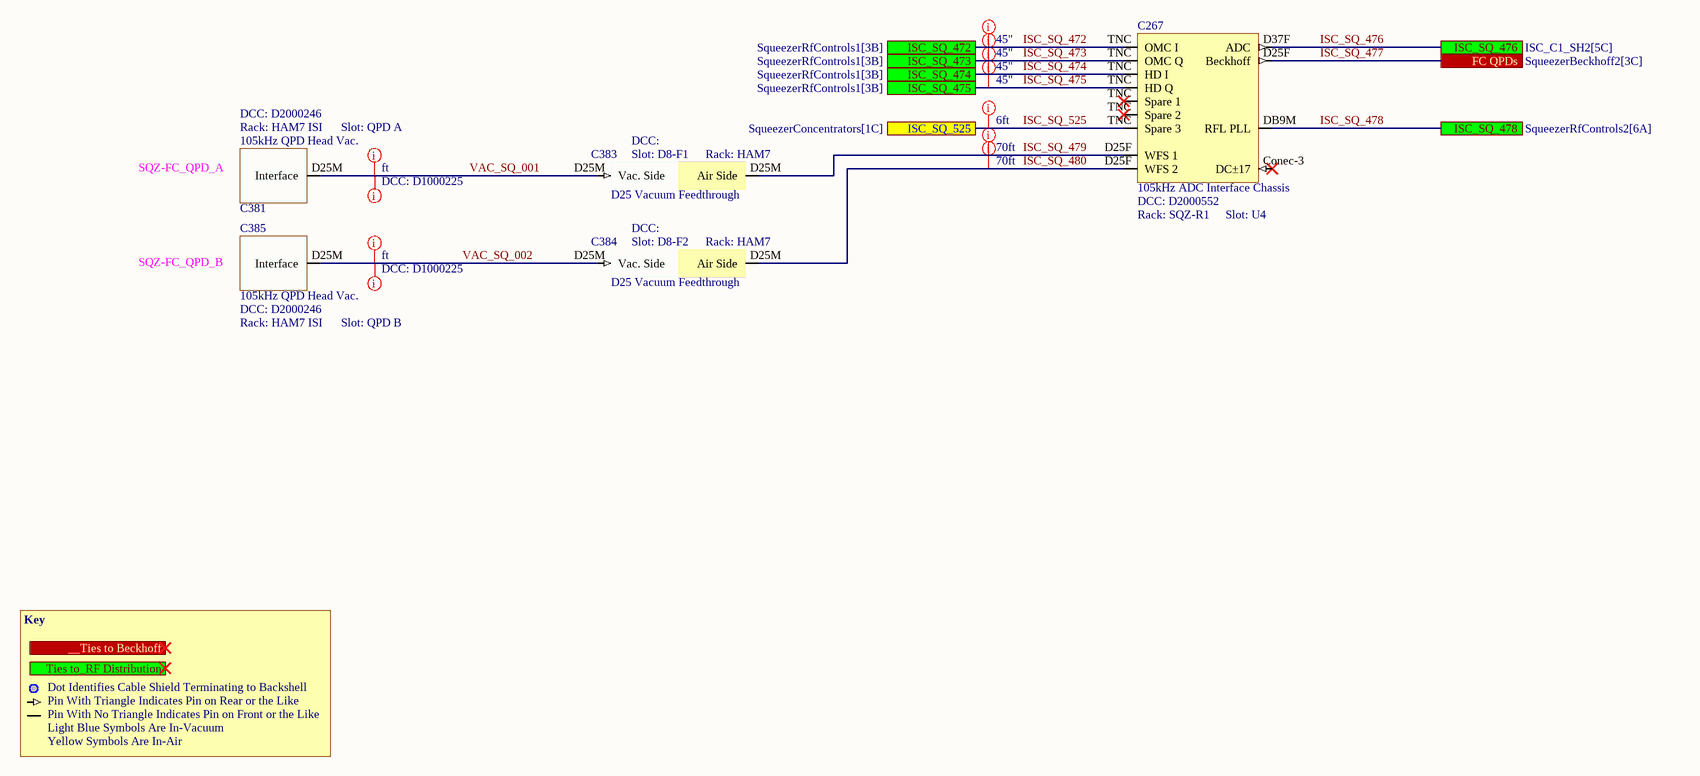
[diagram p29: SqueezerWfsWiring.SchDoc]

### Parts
C267  105kHz ADC Interface Chassis  DCC: D2000552  Rack: SQZ-R1  Slot: U4
C381  105kHz QPD Head Vac.  DCC: D2000246  Rack: HAM7 ISI  Slot: QPD A
C383  D25 Vacuum Feedthrough  Rack: HAM7  Slot: D8-F1
C384  D25 Vacuum Feedthrough  Rack: HAM7  Slot: D8-F2
C385  105kHz QPD Head Vac.  DCC: D2000246  Rack: HAM7 ISI  Slot: QPD B

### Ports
__Ties to Beckhoff, FC QPDs (see SqueezerBeckhoff2[3C]), ISC_SQ_472 (see SqueezerRfControls1[3B]), ISC_SQ_473 (see SqueezerRfControls1[3B]), ISC_SQ_474 (see SqueezerRfControls1[3B]), ISC_SQ_475 (see SqueezerRfControls1[3B]), ISC_SQ_476 (see ISC_C1_SH2[5C]), ISC_SQ_478 (see SqueezerRfControls2[6A]), ISC_SQ_525 (see SqueezerConcentrators[1C]), Ties to_RF Distribution

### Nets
ISC_SQ_472: C267.TNC(OMC_I) ; port ISC_SQ_472
ISC_SQ_473: C267.TNC(OMC_Q) ; port ISC_SQ_473
ISC_SQ_474: C267.TNC(HD_I) ; port ISC_SQ_474
ISC_SQ_475: C267.TNC(HD_Q) ; port ISC_SQ_475
ISC_SQ_476: C267.D37F(ADC) ; port ISC_SQ_476
ISC_SQ_477: C267.D25F(Beckhoff) ; port FC QPDs
ISC_SQ_478: C267.DB9M(RFL_PLL) ; port ISC_SQ_478
ISC_SQ_479: C267.D25F(WFS_1) C383.D25M(Air_Side)
ISC_SQ_480: C267.D25F(WFS_2) C384.D25M(Air_Side)
ISC_SQ_525: C267.TNC(Spare_3) ; port ISC_SQ_525
VAC_SQ_001: C381.D25M(Interface) C383.D25M(Vac._Side)
VAC_SQ_002: C384.D25M(Vac._Side) C385.D25M(Interface)

Not connected (* = marked no-connect by the designer): C267 Conec-3(DC±17)*

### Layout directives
Length: 70ft: ISC_SQ_479, ISC_SQ_480
DCC: D1000225: VAC_SQ_001, VAC_SQ_002
Length: ft: VAC_SQ_001, VAC_SQ_002
Length: 45": ISC_SQ_472, ISC_SQ_473, ISC_SQ_474, ISC_SQ_475
Length: 6ft: ISC_SQ_525

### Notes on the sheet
- SQZ-FC_QPD_A
- SQZ-FC_QPD_B
- Key
- Dot Identifies Cable Shield Terminating to Backshell
- Pin With Triangle Indicates Pin on Rear or the Like
- Pin With No Triangle Indicates Pin on Front or the Like
- Light Blue Symbols Are In-Vacuum
- Yellow Symbols Are In-Air

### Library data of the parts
C267 = 105kHz ADC Interface Chassis: Serial: Sxxxxxxx; System: ISC
C381 C385 = 105kHz QPD Head Vac.: Serial: Sxxxxxxx; System: ISC
C383 C384 = VacFeedD25: Serial: Sxxxxxxx; System: ISC

## Sheet SqueezerInVacControls.SchDoc: Squeezer In-Vacuum Controls
size B; Organization: LIGO Laboratory; Address1: California Institute of Technology; Address2: Massachusetts Institute of Technology; DocumentNumber: D1900511; Revision: V11; SheetNumber: 31; SheetTotal: 39; DrawnBy: R.  Abbott; Engineer: R.  Abbott; PageSetup: Record=PageOptions¦CenterHorizontal=True¦CenterVertical=True¦PrintScale=1.09¦XCorrection=1.00¦YCorrection=1.00¦PrintKind=0¦BorderSize=5000000¦LeftOffset=0¦BottomOffset=0¦Orientation=2¦PaperLength=1000¦PaperWidth=1000¦Scale=100¦PaperSource=7¦PrintQuality=-4¦MediaType=1¦DitherType=10¦PaperKind=11x17¦PrintScaleMode=1
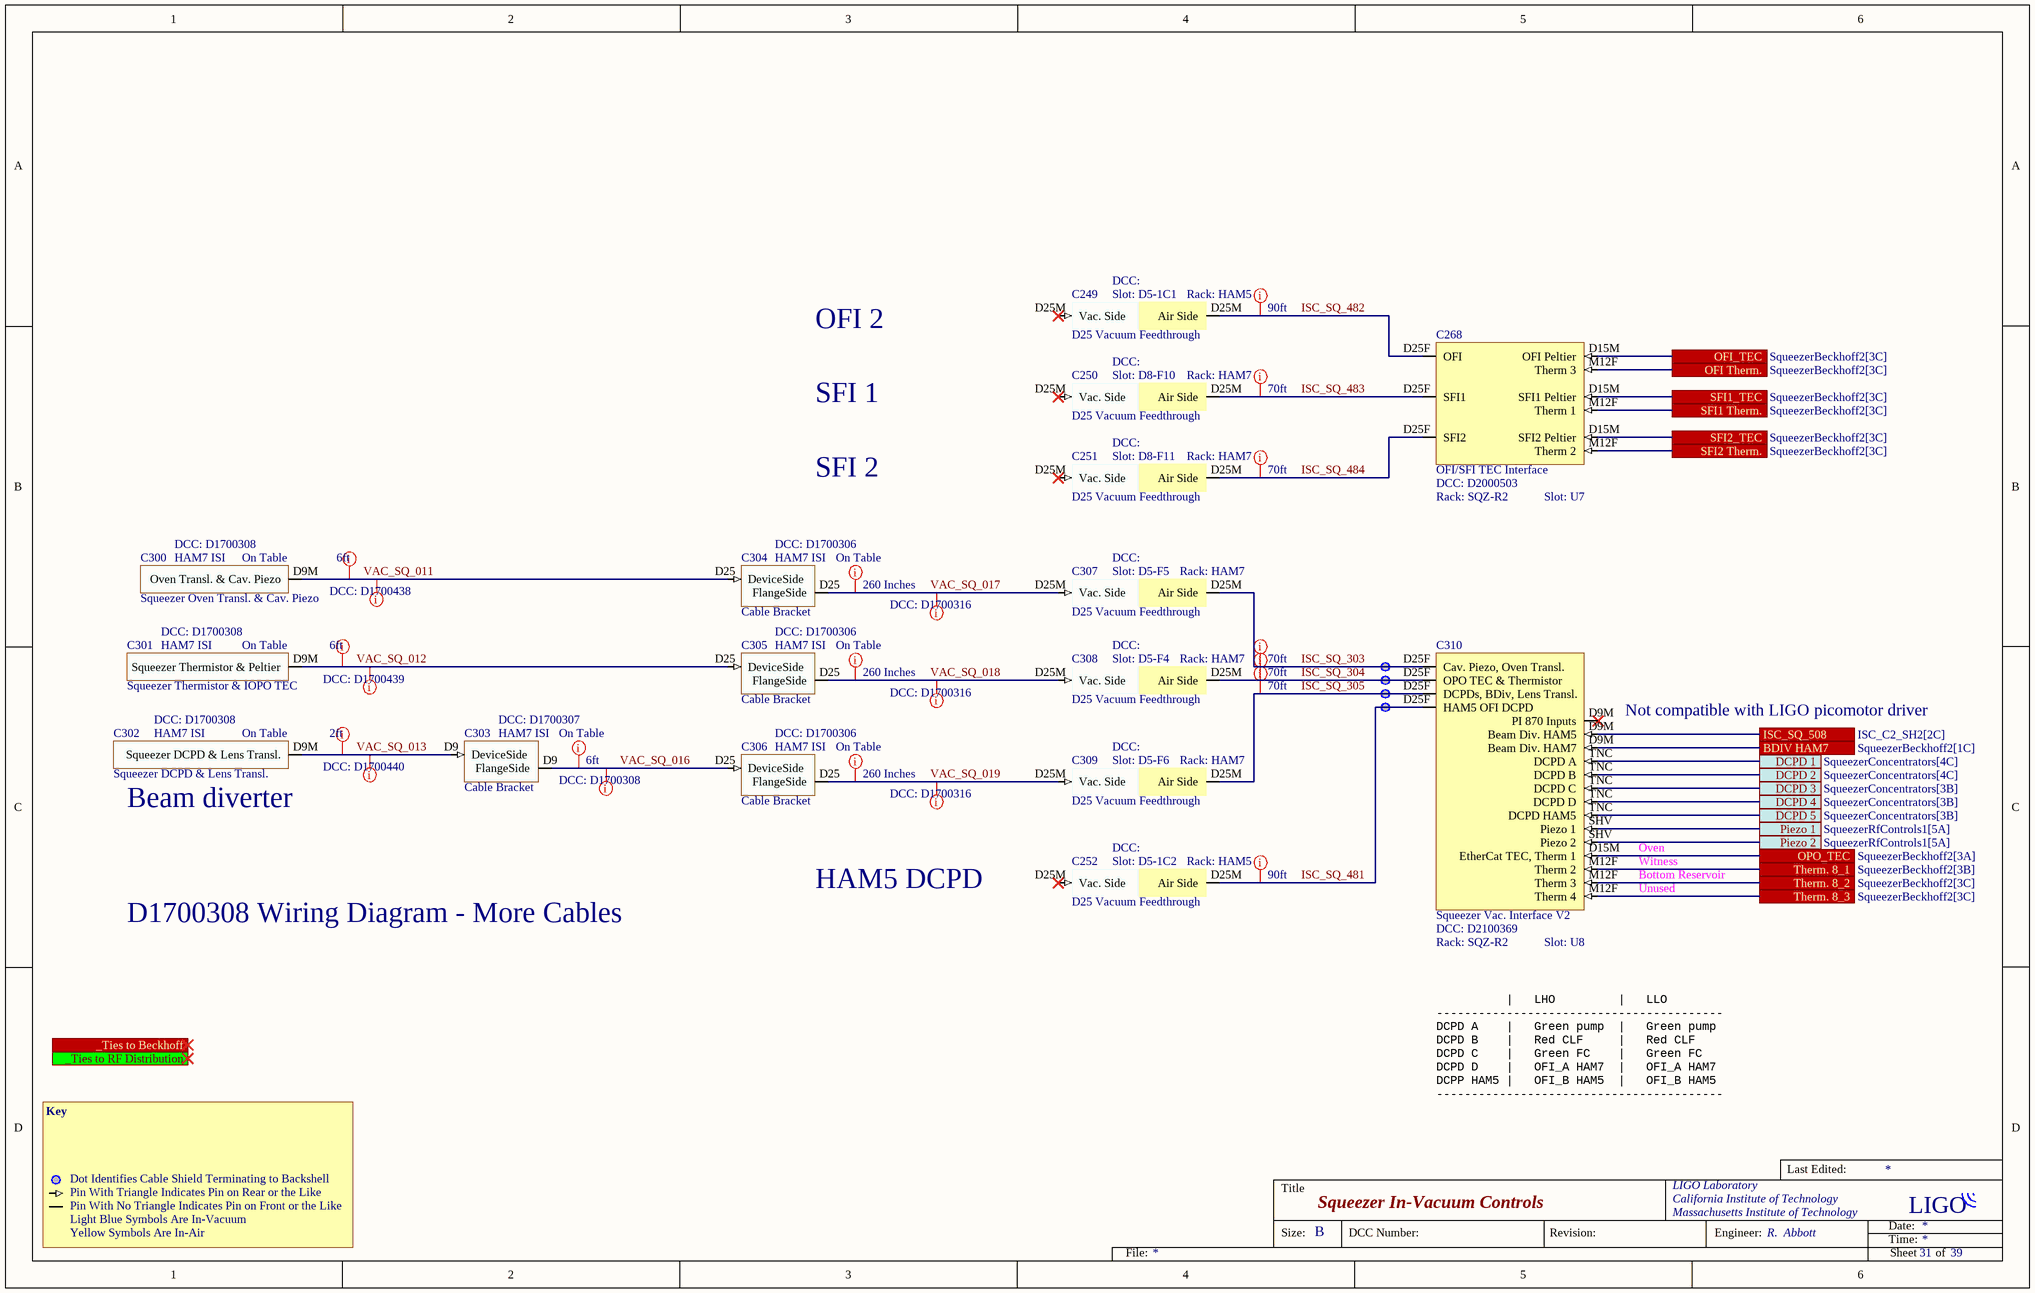
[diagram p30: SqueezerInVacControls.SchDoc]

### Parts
C249  D25 Vacuum Feedthrough  Rack: HAM5  Slot: D5-1C1
C250  D25 Vacuum Feedthrough  Rack: HAM7  Slot: D8-F10
C251  D25 Vacuum Feedthrough  Rack: HAM7  Slot: D8-F11
C252  D25 Vacuum Feedthrough  Rack: HAM5  Slot: D5-1C2
C268  OFI/SFI TEC Interface  DCC: D2000503  Rack: SQZ-R2  Slot: U7
C300  Squeezer Oven Transl. & Cav. Piezo  DCC: D1700308  Rack: HAM7 ISI  Slot: On Table
C301  Squeezer Thermistor & IOPO TEC  DCC: D1700308  Rack: HAM7 ISI  Slot: On Table
C302  Squeezer DCPD & Lens Transl.  DCC: D1700308  Rack: HAM7 ISI  Slot: On Table
C303  Cable Bracket  DCC: D1700307  Rack: HAM7 ISI  Slot: On Table
C304  Cable Bracket  DCC: D1700306  Rack: HAM7 ISI  Slot: On Table
C305  Cable Bracket  DCC: D1700306  Rack: HAM7 ISI  Slot: On Table
C306  Cable Bracket  DCC: D1700306  Rack: HAM7 ISI  Slot: On Table
C307  D25 Vacuum Feedthrough  Rack: HAM7  Slot: D5-F5
C308  D25 Vacuum Feedthrough  Rack: HAM7  Slot: D5-F4
C309  D25 Vacuum Feedthrough  Rack: HAM7  Slot: D5-F6
C310  Squeezer Vac. Interface V2  DCC: D2100369  Rack: SQZ-R2  Slot: U8

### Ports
_Ties to Beckhoff, _Ties to RF Distribution, BDIV HAM7 (see SqueezerBeckhoff2[1C]), DCPD 1 (see SqueezerConcentrators[4C]), DCPD 2 (see SqueezerConcentrators[4C]), DCPD 3 (see SqueezerConcentrators[3B]), DCPD 4 (see SqueezerConcentrators[3B]), DCPD 5 (see SqueezerConcentrators[3B]), ISC_SQ_508 (see ISC_C2_SH2[2C]), OFI Therm. (see SqueezerBeckhoff2[3C]), OFI_TEC (see SqueezerBeckhoff2[3C]), OPO_TEC (see SqueezerBeckhoff2[3A]), Piezo 1 (see SqueezerRfControls1[5A]), Piezo 2 (see SqueezerRfControls1[5A]), SFI1 Therm. (see SqueezerBeckhoff2[3C]), SFI1_TEC (see SqueezerBeckhoff2[3C]), SFI2 Therm. (see SqueezerBeckhoff2[3C]), SFI2_TEC (see SqueezerBeckhoff2[3C]), Therm. 8_1 (see SqueezerBeckhoff2[3B]), Therm. 8_2 (see SqueezerBeckhoff2[3C]), Therm. 8_3 (see SqueezerBeckhoff2[3C])

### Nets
ISC_SQ_98: C310.SHV(Piezo_1) ; port Piezo 1
ISC_SQ_99: C310.SHV(Piezo_2) ; port Piezo 2
ISC_SQ_303: C307.D25M(Air_Side) C310.D25F(Cav._Piezo,_Oven_Transl.)
ISC_SQ_304: C308.D25M(Air_Side) C310.D25F(OPO_TEC_&_Thermistor)
ISC_SQ_305: C309.D25M(Air_Side) C310.D25F(DCPDs,_BDiv,_Lens_Transl.)
ISC_SQ_310: C310.D15M(EtherCat_TEC,_Therm_1) ; port OPO_TEC
ISC_SQ_327: C310.M12F(Therm_2) ; port Therm. 8_1
ISC_SQ_328: C310.M12F(Therm_3) ; port Therm. 8_2
ISC_SQ_329: C310.M12F(Therm_4) ; port Therm. 8_3
ISC_SQ_361: C310.TNC(DCPD_A) ; port DCPD 1
ISC_SQ_362: C310.TNC(DCPD_B) ; port DCPD 2
ISC_SQ_461: C310.TNC(DCPD_C) ; port DCPD 3
ISC_SQ_462: C310.TNC(DCPD_D) ; port DCPD 4
ISC_SQ_463: C310.TNC(DCPD_HAM5) ; port DCPD 5
ISC_SQ_481: C252.D25M(Vac._Side) C310.D25F(HAM5_OFI_DCPD)
ISC_SQ_482: C249.D25M(Vac._Side) C268.D25F(OFI)
ISC_SQ_483: C250.D25M(Vac._Side) C268.D25F(SFI1)
ISC_SQ_484: C251.D25M(Vac._Side) C268.D25F(SFI2)
ISC_SQ_487: C268.D15M(OFI_Peltier) ; port OFI_TEC
ISC_SQ_488: C268.D15M(SFI1_Peltier) ; port SFI1_TEC
ISC_SQ_489: C268.D15M(SFI2_Peltier) ; port SFI2_TEC
ISC_SQ_493: C268.M12F(Therm_3) ; port OFI Therm.
ISC_SQ_494: C268.M12F(Therm_1) ; port SFI1 Therm.
ISC_SQ_495: C268.M12F(Therm_2) ; port SFI2 Therm.
ISC_SQ_508: C310.D9M(Beam_Div._HAM5) ; port ISC_SQ_508
ISC_SQ_524: C310.D9M(Beam_Div._HAM7) ; port BDIV HAM7
VAC_SQ_011: C300.D9M(Oven_Transl._&_Cav._Piezo) C304.D25(DeviceSide)
VAC_SQ_012: C301.D9M(Squeezer_Thermistor_&_Peltier) C305.D25(DeviceSide)
VAC_SQ_013: C302.D9M(Squeezer_DCPD_&_Lens_Transl.) C303.D9(DeviceSide)
VAC_SQ_016: C303.D9(FlangeSide) C306.D25(DeviceSide)
VAC_SQ_017: C304.D25(FlangeSide) C307.D25M(Vac._Side)
VAC_SQ_018: C305.D25(FlangeSide) C308.D25M(Vac._Side)
VAC_SQ_019: C306.D25(FlangeSide) C309.D25M(Vac._Side)

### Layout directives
DCC: D1700438: VAC_SQ_011
DCC: D1700439: VAC_SQ_012
DCC: D1700440: VAC_SQ_013
DCC: D1700308: VAC_SQ_016
Length: 70ft: ISC_SQ_303, ISC_SQ_304, ISC_SQ_305, ISC_SQ_483, ISC_SQ_484
Length: 260 Inches: VAC_SQ_017, VAC_SQ_018, VAC_SQ_019
DCC: D1700316: VAC_SQ_017, VAC_SQ_018, VAC_SQ_019
Length: 6ft: VAC_SQ_011, VAC_SQ_012, VAC_SQ_016
Length: 2ft: VAC_SQ_013
Length: 90ft: ISC_SQ_481, ISC_SQ_482

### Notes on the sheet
- OFI 2
- SFI 1
- SFI 2
- (near C310) Not compatible with LIGO picomotor driver
- (near C302) Beam diverter
- HAM5 DCPD
- Oven
- Witness
- Bottom Reservoir
- Unused
- D1700308 Wiring Diagram - More Cables
- |   LHO         |   LLO
  -----------------------------------------
  DCPD A    |   Green pump  |   Green pump
  DCPD B    |   Red CLF     |   Red CLF
  DCPD C    |   Green FC    |   Green FC
  DCPD D    |   OFI_A HAM7  |   OFI_A HAM7
  DCPP HAM5 |   OFI_B HAM5  |   OFI_B HAM5
  -----------------------------------------
- Key
- Dot Identifies Cable Shield Terminating to Backshell
- Pin With Triangle Indicates Pin on Rear or the Like
- Pin With No Triangle Indicates Pin on Front or the Like
- Light Blue Symbols Are In-Vacuum
- Yellow Symbols Are In-Air

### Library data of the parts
C249-C252 C307-C309 = VacFeedD25: Serial: Sxxxxxxx; System: ISC
C268 = OFI/SFI TEC Interface: Serial: Sxxxxxxx; System: ISC
C300 = Squeezer Oven Transl. & Cav. Piezo: Serial: Sxxxxxxx; System: ISC
C301 = Squeezer Thermistor & Peltier: Serial: Sxxxxxxx; System: ISC
C302 = Squeezer DCPD & Lens Transl.: Serial: Sxxxxxxx; System: ISC
C303 = CabBracket_D9: Serial: Sxxxxxxx; System: ISC
C304-C306 = CabBracket_D25: Serial: Sxxxxxxx; System: ISC
C310 = Squeezer Vac. Interface V2: Serial: Sxxxxxxx; System: ISC

## Sheet SqueezerFiber.SchDoc: Squeezer Fiber Connetctions
size B; Organization: LIGO Laboratory; Address1: California Institute of Technology; Address2: Massachusetts Institute of Technology; DocumentNumber: D1900511; Revision: V11; SheetNumber: 32; SheetTotal: 39; DrawnBy: R.  Abbott; Engineer: R.  Abbott; PageSetup: Record=PageOptions¦CenterHorizontal=True¦CenterVertical=True¦PrintScale=1.09¦XCorrection=1.00¦YCorrection=1.00¦PrintKind=0¦BorderSize=5000000¦LeftOffset=0¦BottomOffset=0¦Orientation=2¦PaperLength=1000¦PaperWidth=1000¦Scale=100¦PaperSource=7¦PrintQuality=-4¦MediaType=1¦DitherType=10¦PaperKind=11x17¦PrintScaleMode=1
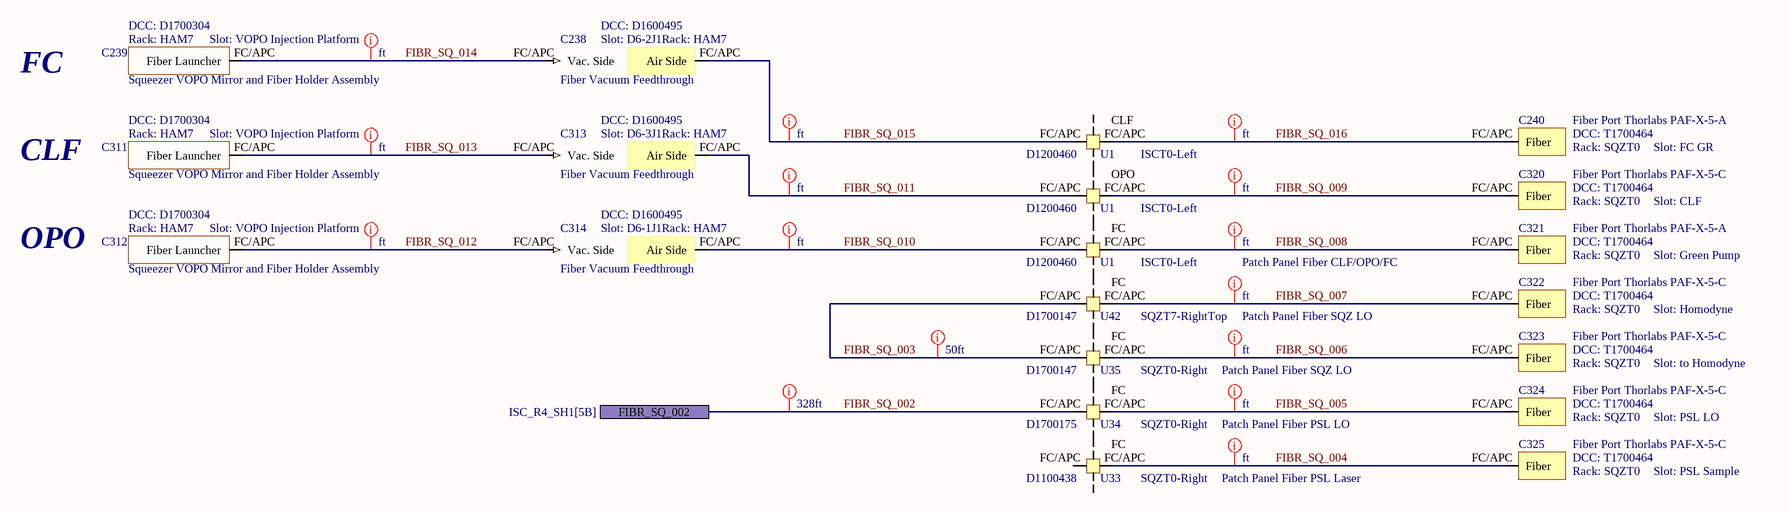
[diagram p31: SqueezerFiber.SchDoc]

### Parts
C238  Fiber Vacuum Feedthrough  DCC: D1600495  Rack: HAM7  Slot: D6-2J1
C239  Squeezer VOPO Mirror and Fiber Holder Assembly  DCC: D1700304  Rack: HAM7  Slot: VOPO Injection Platform
C240  Fiber Port Thorlabs PAF-X-5-A  DCC: T1700464  Rack: SQZT0  Slot: FC GR
C241  DCC: D1200460  Rack: ISCT0-Left  Slot: U1  (hidden comment: Patch Panel Fiber CLF/OPO/FC)  (parts A,B,C of 3)
C311  Squeezer VOPO Mirror and Fiber Holder Assembly  DCC: D1700304  Rack: HAM7  Slot: VOPO Injection Platform
C312  Squeezer VOPO Mirror and Fiber Holder Assembly  DCC: D1700304  Rack: HAM7  Slot: VOPO Injection Platform
C313  Fiber Vacuum Feedthrough  DCC: D1600495  Rack: HAM7  Slot: D6-3J1
C314  Fiber Vacuum Feedthrough  DCC: D1600495  Rack: HAM7  Slot: D6-1J1
C316  Patch Panel Fiber SQZ LO  DCC: D1700147  Rack: SQZT7-RightTop  Slot: U42
C317  Patch Panel Fiber SQZ LO  DCC: D1700147  Rack: SQZT0-Right  Slot: U35
C318  Patch Panel Fiber PSL LO  DCC: D1700175  Rack: SQZT0-Right  Slot: U34
C320  Fiber Port Thorlabs PAF-X-5-C  DCC: T1700464  Rack: SQZT0  Slot: CLF
C321  Fiber Port Thorlabs PAF-X-5-A  DCC: T1700464  Rack: SQZT0  Slot: Green Pump
C322  Fiber Port Thorlabs PAF-X-5-C  DCC: T1700464  Rack: SQZT0  Slot: Homodyne
C323  Fiber Port Thorlabs PAF-X-5-C  DCC: T1700464  Rack: SQZT0  Slot: to Homodyne
C324  Fiber Port Thorlabs PAF-X-5-C  DCC: T1700464  Rack: SQZT0  Slot: PSL LO
C325  Fiber Port Thorlabs PAF-X-5-C  DCC: T1700464  Rack: SQZT0  Slot: PSL Sample
D1100438  Patch Panel Fiber PSL Laser  DCC: D1100438  Rack: SQZT0-Right  Slot: U33

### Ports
FIBR_SQ_002 (see ISC_R4_SH1[5B])

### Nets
FIBR_SQ_002: C318.FC/APC(Fiber) ; port FIBR_SQ_002
FIBR_SQ_003: C316.FC/APC(Fiber) C317.FC/APC(Fiber)
FIBR_SQ_004: C325.FC/APC(Fiber) D1100438.FC/APC(Fiber)
FIBR_SQ_005: C318.FC/APC(Fiber) C324.FC/APC(Fiber)
FIBR_SQ_006: C317.FC/APC(Fiber) C323.FC/APC(Fiber)
FIBR_SQ_007: C316.FC/APC(Fiber) C322.FC/APC(Fiber)
FIBR_SQ_008: C241.FC/APC(OPO) C321.FC/APC(Fiber)
FIBR_SQ_009: C241.FC/APC(OPO) C320.FC/APC(Fiber)
FIBR_SQ_010: C241.FC/APC(OPO) C314.FC/APC(Air_Side)
FIBR_SQ_011: C241.FC/APC(OPO) C313.FC/APC(Air_Side)
FIBR_SQ_012: C312.FC/APC(Fiber_Launcher) C314.FC/APC(Vac._Side)
FIBR_SQ_013: C311.FC/APC(Fiber_Launcher) C313.FC/APC(Vac._Side)
FIBR_SQ_014: C238.FC/APC(Vac._Side) C239.FC/APC(Fiber_Launcher)
FIBR_SQ_015: C238.FC/APC(Air_Side) C241.FC/APC(CLF)
FIBR_SQ_016: C240.FC/APC(Fiber) C241.FC/APC(CLF)

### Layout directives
Length: 328ft: FIBR_SQ_002
Length: 50ft: FIBR_SQ_003
Length: ft: FIBR_SQ_004, FIBR_SQ_005, FIBR_SQ_006, FIBR_SQ_007, FIBR_SQ_008, FIBR_SQ_009, FIBR_SQ_010, FIBR_SQ_011, FIBR_SQ_012, FIBR_SQ_013, FIBR_SQ_014, FIBR_SQ_015, FIBR_SQ_016

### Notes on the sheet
- FC
- CLF
- OPO

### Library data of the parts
C238 C313 C314 = VacFeedFiber: Serial: Sxxxxxxx; System: ISC
C239 C311 C312 = Squeezer VOPO Mirror and Fiber Holder Assembly: Serial: Sxxxxxxx; System: ISC
C240 C320-C325 = Fiber Port Thorlabs PAF Series: Serial: Sxxxxxxx; System: ISC
C241 = Patch Panel Fiber CLF/OPO/FC: Patch Panel (D2000460); Serial: Sxxxxxxx; System: ISC
C316 C317 = Patch Panel Fiber SQZ LO: Patch Panel (D1700147); Serial: Sxxxxxxx; System: ISC
C318 = Patch Panel Fiber PSL LO: Patch Panel (D1700175); Serial: Sxxxxxxx; System: ISC
D1100438 = Patch Panel Fiber PSL Laser: Patch Panel (D1100438); Serial: Sxxxxxxx; System: ISC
